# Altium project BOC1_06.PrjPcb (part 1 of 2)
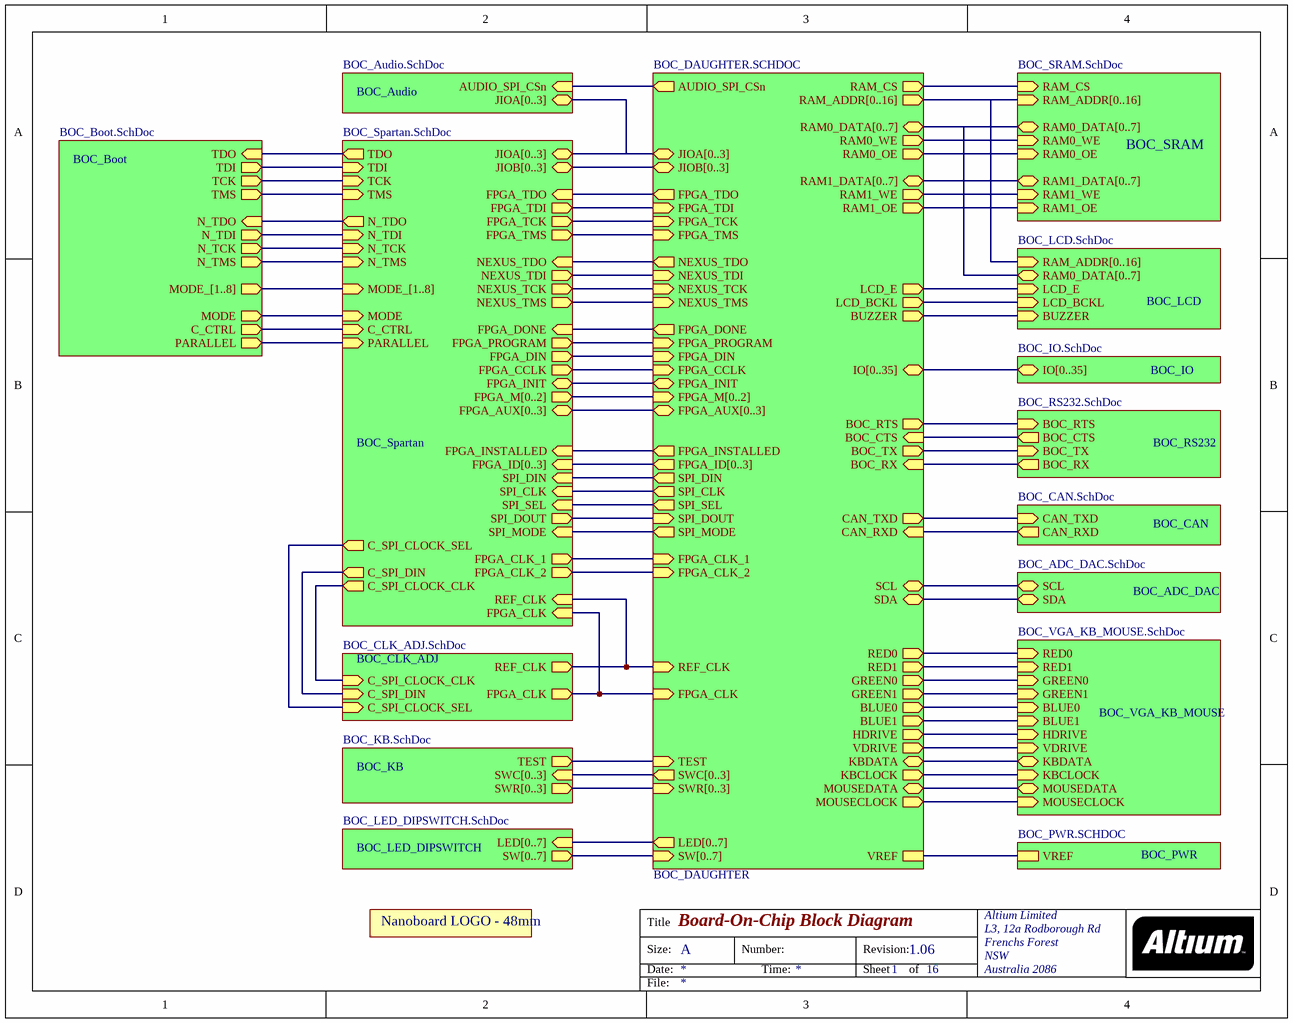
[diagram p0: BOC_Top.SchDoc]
16 sheets, 311 parts. Net scope: hierarchical (ports join the sheet entries above them; power ports are global).
Board file: BOC1_06.PcbDoc
Sheets:
  BOC_Top.SchDoc
    BOC_SRAM = BOC_SRAM.SchDoc
    BOC_IO = BOC_IO.SchDoc
    BOC_KB = BOC_KB.SchDoc
    BOC_PWR = BOC_PWR.SchDoc
    BOC_RS232 = BOC_RS232.SchDoc
    BOC_ADC_DAC = BOC_ADC_DAC.SchDoc
    BOC_CAN = BOC_CAN.SchDoc
    BOC_LED_DIPSWITCH = BOC_LED_DIPSWITCH.SchDoc
    BOC_CLK_ADJ = BOC_CLK_ADJ.SchDoc
    BOC_LCD = BOC_LCD.SchDoc
    BOC_VGA_KB_MOUSE = BOC_VGA_KB_MOUSE.SchDoc
    BOC_Spartan = BOC_Spartan.SchDoc
    BOC_DAUGHTER = BOC_DAUGHTER.SchDoc
    BOC_Boot = BOC_Boot.SchDoc
    BOC_Audio = BOC_Audio.SchDoc

## Sheet BOC_Top.SchDoc: Board-On-Chip Block Diagram
size A; Organization: Altium Limited; Address1: L3, 12a Rodborough Rd; Address2: Frenchs Forest; Address3: NSW; Address4: Australia 2086; Revision: 1.06; SheetNumber: 1; SheetTotal: 16

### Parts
LOGO1  NanoboardLogo48mm  [NanoboardLogo48mm]  (value not drawn)  (graphical)

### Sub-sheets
BOC_ADC_DAC = BOC_ADC_DAC.SchDoc: SCL (bidir), SDA (bidir)
BOC_Audio = BOC_Audio.SchDoc: AUDIO_SPI_CSn (in), JIOA[0..3] (bidir)
BOC_Boot = BOC_Boot.SchDoc: TCK (out), TDO (in), TDI (out), TMS (out), C_CTRL (out), PARALLEL (out), MODE_[1..8] (out), N_TDI (out), N_TDO (in), N_TCK (out), N_TMS (out), MODE (out)
BOC_CAN = BOC_CAN.SchDoc: CAN_TXD (in), CAN_RXD (out)
BOC_CLK_ADJ = BOC_CLK_ADJ.SchDoc: FPGA_CLK (out), REF_CLK (out), C_SPI_CLOCK_SEL (in), C_SPI_DIN (in), C_SPI_CLOCK_CLK (in)
BOC_DAUGHTER = BOC_DAUGHTER.SCHDOC: FPGA_DONE (out), FPGA_PROGRAM (in), FPGA_CCLK (in), FPGA_DIN (in), IO[0..35] (bidir), BOC_RTS (out), BOC_TX (out), BOC_CTS (in), BOC_RX (in), CAN_TXD (out), CAN_RXD (in), JIOA[0..3] (bidir), JIOB[0..3] (bidir), LED[0..7] (out), SW[0..7] (in), LCD_BCKL (out), FPGA_AUX[0..3] (bidir), FPGA_M[0..2] (in), FPGA_TDI (in), FPGA_TCK (in), FPGA_TMS (in), FPGA_TDO (out), RAM_ADDR[0..16] (out), RAM0_DATA[0..7] (bidir), RAM1_DATA[0..7] (bidir), RAM0_OE (out), RAM0_WE (out), RAM1_OE (out), RAM1_WE (out), RAM_CS (out), RED0 (out), RED1 (out), GREEN0 (out), GREEN1 (out), BLUE0 (out), BLUE1 (out), HDRIVE (out), VDRIVE (out), KBDATA (bidir), KBCLOCK (out), MOUSEDATA (bidir), MOUSECLOCK (out), SWC[0..3] (out), SWR[0..3] (in), FPGA_CLK (in), TEST (in), SCL (bidir), SDA (bidir), NEXUS_TDI (in), NEXUS_TCK (in), NEXUS_TMS (in), NEXUS_TDO (out), BUZZER (out), FPGA_INIT (bidir), VREF, SPI_MODE (out), SPI_DOUT (in), SPI_SEL (out), SPI_CLK (out), SPI_DIN (out), FPGA_CLK_1 (in), FPGA_CLK_2 (in), FPGA_INSTALLED (out), REF_CLK (in), FPGA_ID[0..3] (out), LCD_E (out), AUDIO_SPI_CSn (out)
BOC_IO = BOC_IO.SchDoc: IO[0..35] (bidir)
BOC_KB = BOC_KB.SchDoc: SWC[0..3] (in), SWR[0..3] (out), TEST (out)
BOC_LCD = BOC_LCD.SchDoc: RAM0_DATA[0..7] (bidir), LCD_BCKL (in), RAM_ADDR[0..16] (in), BUZZER (in), LCD_E (in)
BOC_LED_DIPSWITCH = BOC_LED_DIPSWITCH.SchDoc: LED[0..7] (in), SW[0..7] (out)
BOC_PWR = BOC_PWR.SCHDOC: VREF
BOC_RS232 = BOC_RS232.SchDoc: BOC_RTS (in), BOC_TX (in), BOC_CTS (out), BOC_RX (out)
BOC_Spartan = BOC_Spartan.SchDoc: FPGA_TDI (out), FPGA_TCK (out), FPGA_TMS (out), FPGA_TDO (in), FPGA_DONE (in), FPGA_PROGRAM (out), FPGA_CCLK (out), FPGA_DIN (out), FPGA_AUX[0..3] (bidir), FPGA_M[0..2] (out), JIOA[0..3] (bidir), JIOB[0..3] (bidir), REF_CLK (in), FPGA_INIT (bidir), NEXUS_TDO (in), NEXUS_TDI (out), NEXUS_TCK (out), NEXUS_TMS (out), FPGA_CLK_1 (out), FPGA_CLK_2 (out), FPGA_INSTALLED (in), SPI_DIN (in), SPI_CLK (in), SPI_SEL (in), SPI_DOUT (out), SPI_MODE (in), C_SPI_CLOCK_CLK (out), C_SPI_DIN (out), C_SPI_CLOCK_SEL (out), FPGA_ID[0..3] (in), TCK (in), TDO (out), TDI (in), TMS (in), C_CTRL (in), PARALLEL (in), MODE_[1..8] (in), N_TDI (in), N_TDO (out), N_TCK (in), N_TMS (in), MODE (in), FPGA_CLK (in)
BOC_SRAM = BOC_SRAM.SchDoc: RAM_ADDR[0..16] (in), RAM1_DATA[0..7] (bidir), RAM0_WE (in), RAM0_OE (in), RAM1_WE (in), RAM1_OE (in), RAM_CS (in), RAM0_DATA[0..7] (bidir)
BOC_VGA_KB_MOUSE = BOC_VGA_KB_MOUSE.SchDoc: RED0 (in), RED1 (in), GREEN0 (in), GREEN1 (in), BLUE0 (in), BLUE1 (in), HDRIVE (in), VDRIVE (in), KBDATA (bidir), KBCLOCK (in), MOUSEDATA (bidir), MOUSECLOCK (in)

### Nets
AUDIO_SPI_CSn: sheet BOC_DAUGHTER/AUDIO_SPI_CSn, sheet BOC_Audio/AUDIO_SPI_CSn
BLUE0: sheet BOC_VGA_KB_MOUSE/BLUE0, sheet BOC_DAUGHTER/BLUE0
BLUE1: sheet BOC_VGA_KB_MOUSE/BLUE1, sheet BOC_DAUGHTER/BLUE1
BOC_CTS: sheet BOC_RS232/BOC_CTS, sheet BOC_DAUGHTER/BOC_CTS
BOC_RTS: sheet BOC_RS232/BOC_RTS, sheet BOC_DAUGHTER/BOC_RTS
BOC_RX: sheet BOC_RS232/BOC_RX, sheet BOC_DAUGHTER/BOC_RX
BOC_TX: sheet BOC_RS232/BOC_TX, sheet BOC_DAUGHTER/BOC_TX
BUZZER: sheet BOC_LCD/BUZZER, sheet BOC_DAUGHTER/BUZZER
C_CTRL: sheet BOC_Spartan/C_CTRL, sheet BOC_Boot/C_CTRL
C_SPI_CLOCK_CLK: sheet BOC_CLK_ADJ/C_SPI_CLOCK_CLK, sheet BOC_Spartan/C_SPI_CLOCK_CLK
C_SPI_CLOCK_SEL: sheet BOC_CLK_ADJ/C_SPI_CLOCK_SEL, sheet BOC_Spartan/C_SPI_CLOCK_SEL
C_SPI_DIN: sheet BOC_CLK_ADJ/C_SPI_DIN, sheet BOC_Spartan/C_SPI_DIN
CAN_RXD: sheet BOC_CAN/CAN_RXD, sheet BOC_DAUGHTER/CAN_RXD
CAN_TXD: sheet BOC_CAN/CAN_TXD, sheet BOC_DAUGHTER/CAN_TXD
FPGA_CCLK: sheet BOC_Spartan/FPGA_CCLK, sheet BOC_DAUGHTER/FPGA_CCLK
FPGA_CLK: sheet BOC_CLK_ADJ/FPGA_CLK, sheet BOC_Spartan/FPGA_CLK, sheet BOC_DAUGHTER/FPGA_CLK
FPGA_CLK_1: sheet BOC_Spartan/FPGA_CLK_1, sheet BOC_DAUGHTER/FPGA_CLK_1
FPGA_CLK_2: sheet BOC_Spartan/FPGA_CLK_2, sheet BOC_DAUGHTER/FPGA_CLK_2
FPGA_DIN: sheet BOC_Spartan/FPGA_DIN, sheet BOC_DAUGHTER/FPGA_DIN
FPGA_DONE: sheet BOC_Spartan/FPGA_DONE, sheet BOC_DAUGHTER/FPGA_DONE
FPGA_INIT: sheet BOC_Spartan/FPGA_INIT, sheet BOC_DAUGHTER/FPGA_INIT
FPGA_INSTALLED: sheet BOC_Spartan/FPGA_INSTALLED, sheet BOC_DAUGHTER/FPGA_INSTALLED
FPGA_PROGRAM: sheet BOC_Spartan/FPGA_PROGRAM, sheet BOC_DAUGHTER/FPGA_PROGRAM
FPGA_TCK: sheet BOC_Spartan/FPGA_TCK, sheet BOC_DAUGHTER/FPGA_TCK
FPGA_TDI: sheet BOC_Spartan/FPGA_TDI, sheet BOC_DAUGHTER/FPGA_TDI
FPGA_TDO: sheet BOC_Spartan/FPGA_TDO, sheet BOC_DAUGHTER/FPGA_TDO
FPGA_TMS: sheet BOC_Spartan/FPGA_TMS, sheet BOC_DAUGHTER/FPGA_TMS
GREEN0: sheet BOC_VGA_KB_MOUSE/GREEN0, sheet BOC_DAUGHTER/GREEN0
GREEN1: sheet BOC_VGA_KB_MOUSE/GREEN1, sheet BOC_DAUGHTER/GREEN1
HDRIVE: sheet BOC_VGA_KB_MOUSE/HDRIVE, sheet BOC_DAUGHTER/HDRIVE
KBCLOCK: sheet BOC_VGA_KB_MOUSE/KBCLOCK, sheet BOC_DAUGHTER/KBCLOCK
KBDATA: sheet BOC_VGA_KB_MOUSE/KBDATA, sheet BOC_DAUGHTER/KBDATA
LCD_BCKL: sheet BOC_LCD/LCD_BCKL, sheet BOC_DAUGHTER/LCD_BCKL
LCD_E: sheet BOC_LCD/LCD_E, sheet BOC_DAUGHTER/LCD_E
MODE: sheet BOC_Spartan/MODE, sheet BOC_Boot/MODE
MOUSECLOCK: sheet BOC_VGA_KB_MOUSE/MOUSECLOCK, sheet BOC_DAUGHTER/MOUSECLOCK
MOUSEDATA: sheet BOC_VGA_KB_MOUSE/MOUSEDATA, sheet BOC_DAUGHTER/MOUSEDATA
N_TCK: sheet BOC_Spartan/N_TCK, sheet BOC_Boot/N_TCK
N_TDI: sheet BOC_Spartan/N_TDI, sheet BOC_Boot/N_TDI
N_TDO: sheet BOC_Spartan/N_TDO, sheet BOC_Boot/N_TDO
N_TMS: sheet BOC_Spartan/N_TMS, sheet BOC_Boot/N_TMS
NEXUS_TCK: sheet BOC_Spartan/NEXUS_TCK, sheet BOC_DAUGHTER/NEXUS_TCK
NEXUS_TDI: sheet BOC_Spartan/NEXUS_TDI, sheet BOC_DAUGHTER/NEXUS_TDI
NEXUS_TDO: sheet BOC_Spartan/NEXUS_TDO, sheet BOC_DAUGHTER/NEXUS_TDO
NEXUS_TMS: sheet BOC_Spartan/NEXUS_TMS, sheet BOC_DAUGHTER/NEXUS_TMS
PARALLEL: sheet BOC_Spartan/PARALLEL, sheet BOC_Boot/PARALLEL
RAM0_OE: sheet BOC_SRAM/RAM0_OE, sheet BOC_DAUGHTER/RAM0_OE
RAM0_WE: sheet BOC_SRAM/RAM0_WE, sheet BOC_DAUGHTER/RAM0_WE
RAM1_OE: sheet BOC_SRAM/RAM1_OE, sheet BOC_DAUGHTER/RAM1_OE
RAM1_WE: sheet BOC_SRAM/RAM1_WE, sheet BOC_DAUGHTER/RAM1_WE
RAM_CS: sheet BOC_SRAM/RAM_CS, sheet BOC_DAUGHTER/RAM_CS
RED0: sheet BOC_VGA_KB_MOUSE/RED0, sheet BOC_DAUGHTER/RED0
RED1: sheet BOC_VGA_KB_MOUSE/RED1, sheet BOC_DAUGHTER/RED1
REF_CLK: sheet BOC_CLK_ADJ/REF_CLK, sheet BOC_Spartan/REF_CLK, sheet BOC_DAUGHTER/REF_CLK
SCL: sheet BOC_ADC_DAC/SCL, sheet BOC_DAUGHTER/SCL
SDA: sheet BOC_ADC_DAC/SDA, sheet BOC_DAUGHTER/SDA
SPI_CLK: sheet BOC_Spartan/SPI_CLK, sheet BOC_DAUGHTER/SPI_CLK
SPI_DIN: sheet BOC_Spartan/SPI_DIN, sheet BOC_DAUGHTER/SPI_DIN
SPI_DOUT: sheet BOC_Spartan/SPI_DOUT, sheet BOC_DAUGHTER/SPI_DOUT
SPI_MODE: sheet BOC_Spartan/SPI_MODE, sheet BOC_DAUGHTER/SPI_MODE
SPI_SEL: sheet BOC_Spartan/SPI_SEL, sheet BOC_DAUGHTER/SPI_SEL
TCK: sheet BOC_Spartan/TCK, sheet BOC_Boot/TCK
TDI: sheet BOC_Spartan/TDI, sheet BOC_Boot/TDI
TDO: sheet BOC_Spartan/TDO, sheet BOC_Boot/TDO
TEST: sheet BOC_KB/TEST, sheet BOC_DAUGHTER/TEST
TMS: sheet BOC_Spartan/TMS, sheet BOC_Boot/TMS
VDRIVE: sheet BOC_VGA_KB_MOUSE/VDRIVE, sheet BOC_DAUGHTER/VDRIVE
VREF: sheet BOC_PWR/VREF, sheet BOC_DAUGHTER/VREF

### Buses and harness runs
bus sheet BOC_Audio/JIOA[0..3] = sheet BOC_DAUGHTER/JIOA[0..3] = sheet BOC_Spartan/JIOA[0..3]
bus sheet BOC_Boot/MODE_[1..8] = sheet BOC_Spartan/MODE_[1..8]
bus sheet BOC_DAUGHTER/FPGA_AUX[0..3] = sheet BOC_Spartan/FPGA_AUX[0..3]
bus sheet BOC_DAUGHTER/FPGA_ID[0..3] = sheet BOC_Spartan/FPGA_ID[0..3]
bus sheet BOC_DAUGHTER/FPGA_M[0..2] = sheet BOC_Spartan/FPGA_M[0..2]
bus sheet BOC_DAUGHTER/IO[0..35] = sheet BOC_IO/IO[0..35]
bus sheet BOC_DAUGHTER/JIOB[0..3] = sheet BOC_Spartan/JIOB[0..3]
bus sheet BOC_DAUGHTER/LED[0..7] = sheet BOC_LED_DIPSWITCH/LED[0..7]
bus sheet BOC_DAUGHTER/RAM0_DATA[0..7] = sheet BOC_LCD/RAM0_DATA[0..7] = sheet BOC_SRAM/RAM0_DATA[0..7]
bus sheet BOC_DAUGHTER/RAM1_DATA[0..7] = sheet BOC_SRAM/RAM1_DATA[0..7]
bus sheet BOC_DAUGHTER/RAM_ADDR[0..16] = sheet BOC_LCD/RAM_ADDR[0..16] = sheet BOC_SRAM/RAM_ADDR[0..16]
bus sheet BOC_DAUGHTER/SW[0..7] = sheet BOC_LED_DIPSWITCH/SW[0..7]
bus sheet BOC_DAUGHTER/SWC[0..3] = sheet BOC_KB/SWC[0..3]
bus sheet BOC_DAUGHTER/SWR[0..3] = sheet BOC_KB/SWR[0..3]

## Sheet BOC_SRAM.SchDoc: Board-On-Chip Static Ram 128k
size A; Organization: Altium Limited; Address1: L3, 12a Rodborough Rd; Address2: Frenchs Forest; Address3: NSW; Address4: Australia 2086; Revision: 1.06; SheetNumber: 9; SheetTotal: 16
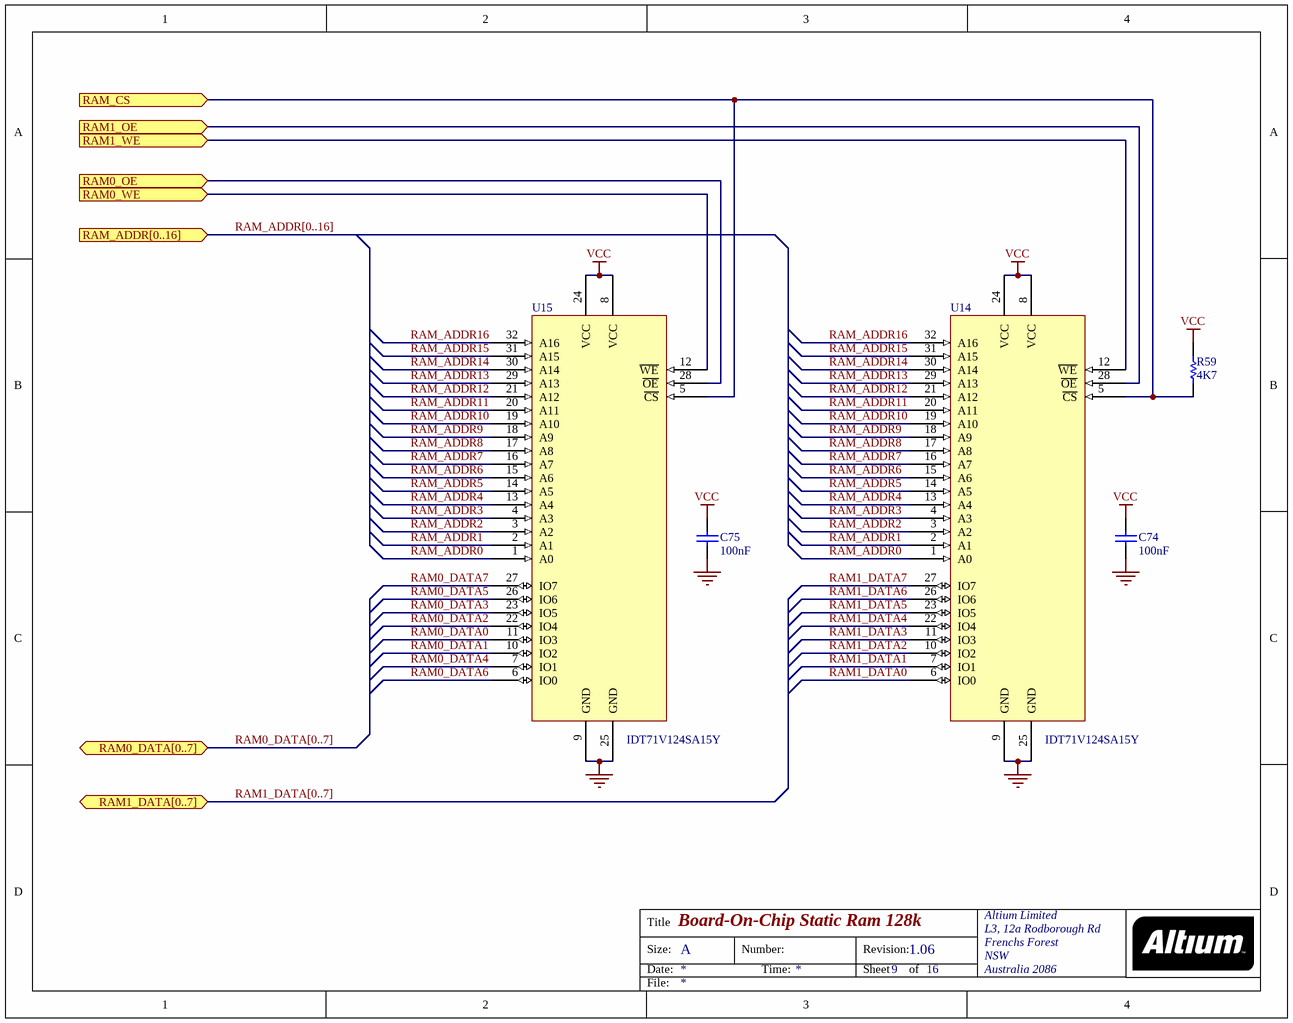
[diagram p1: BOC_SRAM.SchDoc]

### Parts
C74  100nF  [CC2012-0805]
C75  100nF  [CC2012-0805]
R59  4K7  [CC2012-0805]
U14  IDT71V124SA15Y  [SO-J32]
U15  IDT71V124SA15Y  [SO-J32]

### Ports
RAM0_DATA[0..7] (bidir), RAM0_OE (in), RAM0_WE (in), RAM1_DATA[0..7] (bidir), RAM1_OE (in), RAM1_WE (in), RAM_ADDR[0..16] (in), RAM_CS (in)

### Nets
GND: C74.2 C75.2 U14.9(GND) U14.25(GND) U15.9(GND) U15.25(GND)
VCC: C74.1 C75.1 R59.1 U14.8(VCC) U14.24(VCC) U15.8(VCC) U15.24(VCC)
RAM0_DATA0: U15.11(IO3)
RAM0_DATA1: U15.10(IO2)
RAM0_DATA2: U15.22(IO4)
RAM0_DATA3: U15.23(IO5)
RAM0_DATA4: U15.7(IO1)
RAM0_DATA5: U15.26(IO6)
RAM0_DATA6: U15.6(IO0)
RAM0_DATA7: U15.27(IO7)
RAM0_OE: U15.28(~{OE}) ; port RAM0_OE
RAM0_WE: U15.12(~{WE}) ; port RAM0_WE
RAM1_DATA0: U14.6(IO0)
RAM1_DATA1: U14.7(IO1)
RAM1_DATA2: U14.10(IO2)
RAM1_DATA3: U14.11(IO3)
RAM1_DATA4: U14.22(IO4)
RAM1_DATA5: U14.23(IO5)
RAM1_DATA6: U14.26(IO6)
RAM1_DATA7: U14.27(IO7)
RAM1_OE: U14.28(~{OE}) ; port RAM1_OE
RAM1_WE: U14.12(~{WE}) ; port RAM1_WE
RAM_ADDR0: U14.1(A0) U15.1(A0)
RAM_ADDR1: U14.2(A1) U15.2(A1)
RAM_ADDR2: U14.3(A2) U15.3(A2)
RAM_ADDR3: U14.4(A3) U15.4(A3)
RAM_ADDR4: U14.13(A4) U15.13(A4)
RAM_ADDR5: U14.14(A5) U15.14(A5)
RAM_ADDR6: U14.15(A6) U15.15(A6)
RAM_ADDR7: U14.16(A7) U15.16(A7)
RAM_ADDR8: U14.17(A8) U15.17(A8)
RAM_ADDR9: U14.18(A9) U15.18(A9)
RAM_ADDR10: U14.19(A10) U15.19(A10)
RAM_ADDR11: U14.20(A11) U15.20(A11)
RAM_ADDR12: U14.21(A12) U15.21(A12)
RAM_ADDR13: U14.29(A13) U15.29(A13)
RAM_ADDR14: U14.30(A14) U15.30(A14)
RAM_ADDR15: U14.31(A15) U15.31(A15)
RAM_ADDR16: U14.32(A16) U15.32(A16)
RAM_CS: R59.2 U14.5(~{CS}) U15.5(~{CS}) ; port RAM_CS

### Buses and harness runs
bus RAM0_DATA[0..7] = port RAM0_DATA[0..7]
bus RAM1_DATA[0..7] = port RAM1_DATA[0..7]
bus RAM_ADDR[0..16] = port RAM_ADDR[0..16]

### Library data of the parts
C74 C75 = CAP: Capacitor; Fitted: True
R59 = RES: Resistor; Fitted: True
U14 U15 = IDT71V124SA15Y: 128K x 8 bit Fast Static RAM; Fitted: True

## Sheet BOC_IO.SchDoc: Board-On-Chip User Header Ports
size A; Organization: Altium Limited; Address1: L3, 12a Rodborough Rd; Address2: Frenchs Forest; Address3: NSW; Address4: Australia 2086; Revision: 1.06; SheetNumber: 11; SheetTotal: 16
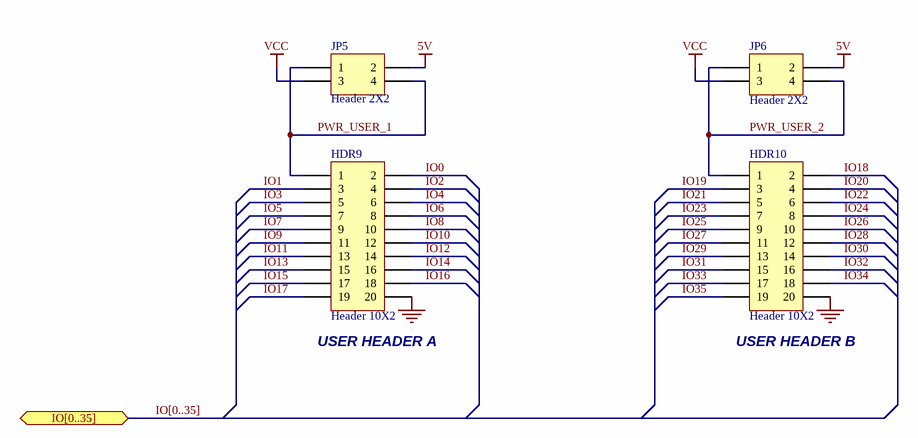
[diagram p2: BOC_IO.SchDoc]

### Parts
HDR9  Header 10X2  [HDR2X10]
HDR10  Header 10X2  [HDR2X10]
JP5  Header 2X2  [HDR2X2_B]
JP6  Header 2X2  [HDR2X2_B]

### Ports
IO[0..35] (bidir)

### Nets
5V: JP5.2 JP6.2
GND: HDR9.20 HDR10.20
VCC: JP5.3 JP6.3
IO0: HDR9.2
IO1: HDR9.3
IO2: HDR9.4
IO3: HDR9.5
IO4: HDR9.6
IO5: HDR9.7
IO6: HDR9.8
IO7: HDR9.9
IO8: HDR9.10
IO9: HDR9.11
IO10: HDR9.12
IO11: HDR9.13
IO12: HDR9.14
IO13: HDR9.15
IO14: HDR9.16
IO15: HDR9.17
IO16: HDR9.18
IO17: HDR9.19
IO18: HDR10.2
IO19: HDR10.3
IO20: HDR10.4
IO21: HDR10.5
IO22: HDR10.6
IO23: HDR10.7
IO24: HDR10.8
IO25: HDR10.9
IO26: HDR10.10
IO27: HDR10.11
IO28: HDR10.12
IO29: HDR10.13
IO30: HDR10.14
IO31: HDR10.15
IO32: HDR10.16
IO33: HDR10.17
IO34: HDR10.18
IO35: HDR10.19
PWR_USER_1: HDR9.1 JP5.1 JP5.4
PWR_USER_2: HDR10.1 JP6.1 JP6.4

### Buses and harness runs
bus IO[0..35] = port IO[0..35]

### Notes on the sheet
- (near HDR9) USER HEADER A
- (near HDR10) USER HEADER B

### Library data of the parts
HDR9 HDR10 = Header 10X2: Header, 10-Pin, Dual row; Manufacturer: Generic Components; Class I: Connector; Fitted: True
JP5 JP6 = Header 2X2: Header, 2-Pin, Dual row; Manufacturer: Generic Components; Class I: Connector; Fitted: True

## Sheet BOC_KB.SchDoc: Board-On-Chip Keyboard
size A; Organization: Altium Limited; Address1: L3, 12a Rodborough Rd; Address2: Frenchs Forest; Address3: NSW; Address4: Australia 2086; Revision: 1.06; SheetNumber: 6; SheetTotal: 16
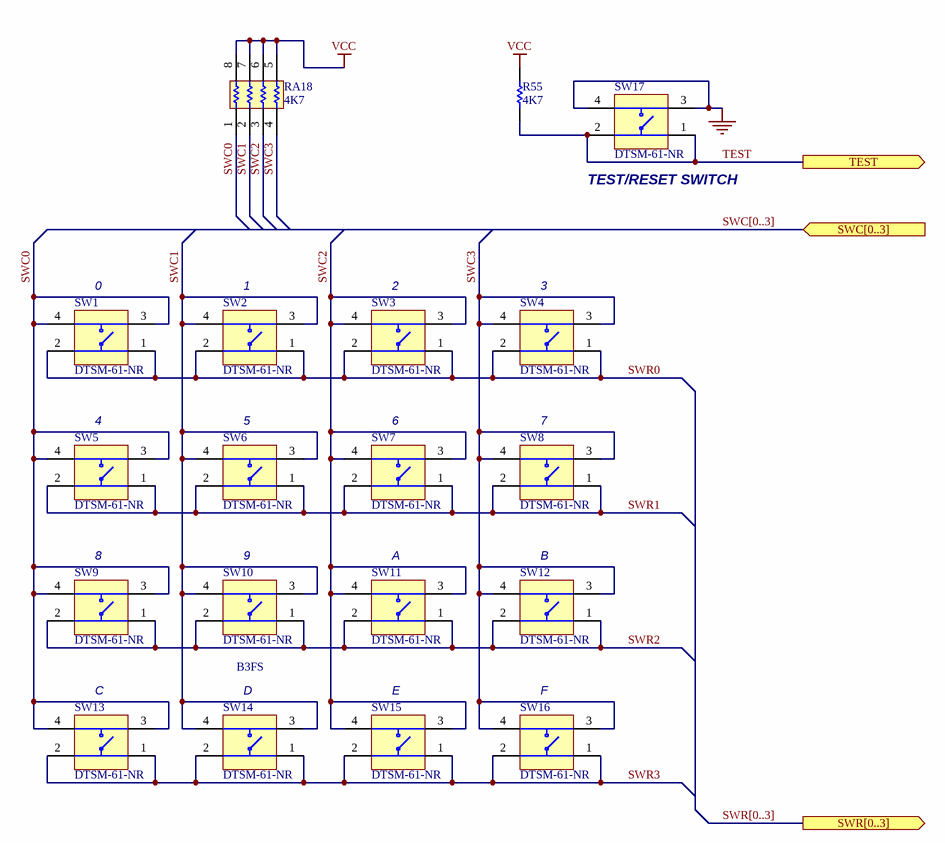
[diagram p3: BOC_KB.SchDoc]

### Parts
R55  4K7  [CC2012-0805]
RA18  4K7  [MNR34]
SW1  DTSM-61-NR  [B3FS_SWITCH]
SW2  DTSM-61-NR  [B3FS_SWITCH]
SW3  DTSM-61-NR  [B3FS_SWITCH]
SW4  DTSM-61-NR  [B3FS_SWITCH]
SW5  DTSM-61-NR  [B3FS_SWITCH]
SW6  DTSM-61-NR  [B3FS_SWITCH]
SW7  DTSM-61-NR  [B3FS_SWITCH]
SW8  DTSM-61-NR  [B3FS_SWITCH]
SW9  DTSM-61-NR  [B3FS_SWITCH]
SW10  DTSM-61-NR  [B3FS_SWITCH]
SW11  DTSM-61-NR  [B3FS_SWITCH]
SW12  DTSM-61-NR  [B3FS_SWITCH]
SW13  DTSM-61-NR  [B3FS_SWITCH]
SW14  DTSM-61-NR  [B3FS_SWITCH]
SW15  DTSM-61-NR  [B3FS_SWITCH]
SW16  DTSM-61-NR  [B3FS_SWITCH]
SW17  DTSM-61-NR  [B3FS_SWITCH]

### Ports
SWC[0..3] (in), SWR[0..3] (out), TEST (out)

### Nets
GND: SW17.3 SW17.4
VCC: R55.1 RA18.5 RA18.6 RA18.7 RA18.8
SWC0: RA18.1 SW1.3 SW1.4 SW5.3 SW5.4 SW9.3 SW9.4 SW13.3 SW13.4
SWC1: RA18.2 SW2.3 SW2.4 SW6.3 SW6.4 SW10.3 SW10.4 SW14.3 SW14.4
SWC2: RA18.3 SW3.3 SW3.4 SW7.3 SW7.4 SW11.3 SW11.4 SW15.3 SW15.4
SWC3: RA18.4 SW4.3 SW4.4 SW8.3 SW8.4 SW12.3 SW12.4 SW16.3 SW16.4
SWR0: SW1.1 SW1.2 SW2.1 SW2.2 SW3.1 SW3.2 SW4.1 SW4.2
SWR1: SW5.1 SW5.2 SW6.1 SW6.2 SW7.1 SW7.2 SW8.1 SW8.2
SWR2: SW9.1 SW9.2 SW10.1 SW10.2 SW11.1 SW11.2 SW12.1 SW12.2
SWR3: SW13.1 SW13.2 SW14.1 SW14.2 SW15.1 SW15.2 SW16.1 SW16.2
TEST: R55.2 SW17.1 SW17.2 ; port TEST

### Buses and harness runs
bus SWC[0..3] = port SWC[0..3]
bus SWR[0..3] = port SWR[0..3]

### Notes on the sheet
- (near SW17) TEST/RESET SWITCH
- (near SW1) 0
- (near SW2) 1
- (near SW3) 2
- (near SW4) 3
- (near SW5) 4
- (near SW6) 5
- (near SW7) 6
- (near SW8) 7
- (near SW9) 8
- (near SW10) 9
- (near SW11) A
- (near SW12) B
- (near SW13) C
- (near SW14) D
- (near SW15) E
- (near SW16) F

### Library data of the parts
R55 = RES: Resistor; Fitted: True
RA18 = MNR34: 3216x4 Resistor Array; Fitted: True
SW1-SW17 = B3FS: SPNA SMD Keyboard Switch; Fitted: True

## Sheet BOC_PWR.SchDoc: Board-On-Chip Power Supply
size A; Organization: Altium Limited; Address1: L3, 12a Rodborough Rd; Address2: Frenchs Forest; Address3: NSW; Address4: Australia 2086; Revision: 1.06; SheetNumber: 16; SheetTotal: 16
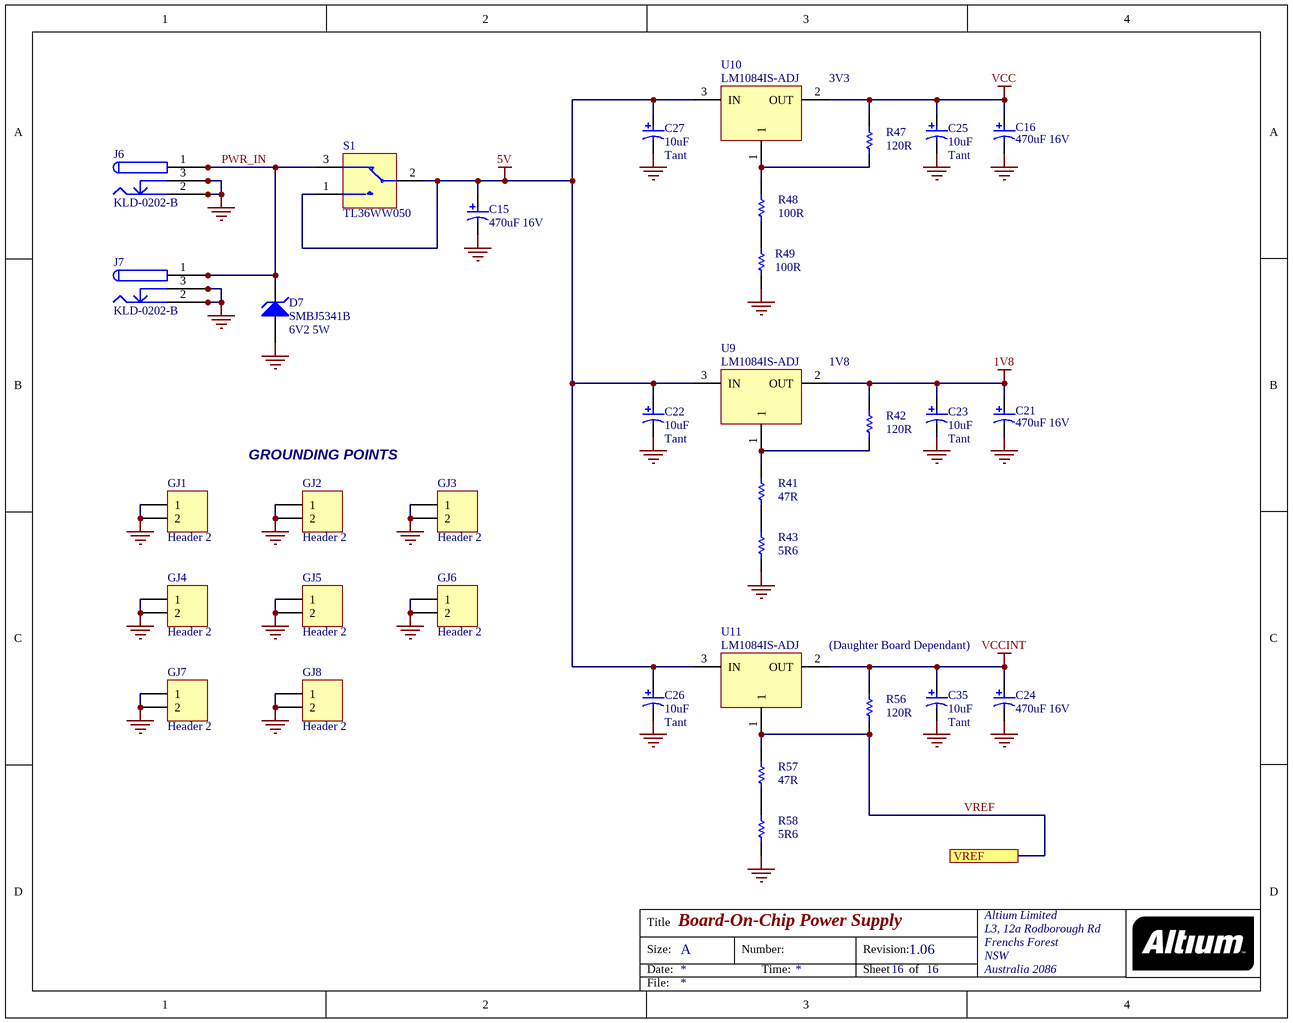
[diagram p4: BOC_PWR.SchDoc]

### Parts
C15  470uF 16V  [RB8/3.5]
C16  470uF 16V  [RB8/3.5]
C21  470uF 16V  [RB8/3.5]
C22  10uF  Capacitor Type: Tant  [MCCT-B]
C23  10uF  Capacitor Type: Tant  [MCCT-B]
C24  470uF 16V  [RB8/3.5]
C25  10uF  Capacitor Type: Tant  [MCCT-B]
C26  10uF  Capacitor Type: Tant  [MCCT-B]
C27  10uF  Capacitor Type: Tant  [MCCT-B]
C35  10uF  Capacitor Type: Tant  [MCCT-B]
D7  SMBJ5341B  Part Description: 6V2 5W  [DO214]
GJ1  Header 2  [HDR1X2]
GJ2  Header 2  [HDR1X2]
GJ3  Header 2  [HDR1X2]
GJ4  Header 2  [HDR1X2]
GJ5  Header 2  [HDR1X2]
GJ6  Header 2  [HDR1X2]
GJ7  Header 2  [HDR1X2]
GJ8  Header 2  [HDR1X2]
J6  KLD-0202-B  [KLD-0202]
J7  KLD-0202-B  [KLD-0202]
R41  47R  [CC2012-0805]
R42  120R  [CC2012-0805]
R43  5R6  [CC2012-0805]
R47  120R  [CC2012-0805]
R48  100R  [CC2012-0805]
R49  100R  [CC2012-0805]
R56  120R  [CC2012-0805]
R57  47R  [CC2012-0805]
R58  5R6  [CC2012-0805]
S1  TL36WW050  [TL36WW15050]
U9  LM1084IS-ADJ  [TO-263]
U10  LM1084IS-ADJ  [TO-263]
U11  LM1084IS-ADJ  [TO-263]

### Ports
VREF

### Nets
1V8: C21.1 C23.1 R42.1 U9.2(OUT)
5V: C15.1 C22.1 C26.1 C27.1 S1.1 S1.2 U9.3(IN) U10.3(IN) U11.3(IN)
GND: C15.2 C16.2 C21.2 C22.2 C23.2 C24.2 C25.2 C26.2 C27.2 C35.2 D7.1(A) GJ1.1 GJ1.2 GJ2.1 GJ2.2 GJ3.1 GJ3.2 GJ4.1 GJ4.2 GJ5.1 GJ5.2 GJ6.1 GJ6.2 GJ7.1 GJ7.2 GJ8.1 GJ8.2 J6.2 J6.2A J6.2B J6.3 J6.3A J6.3B J7.2 J7.2A J7.2B J7.3 J7.3A J7.3B R43.2 R49.1 R58.2
VCC: C16.1 C25.1 R47.1 U10.2(OUT)
VCCINT: C24.1 C35.1 R56.1 U11.2(OUT)
PWR_IN: D7.2(K) J6.1 J6.1A J6.1B J7.1 J7.1A J7.1B S1.3
VREF: R56.2 R57.1 U11.1 ; port VREF
NetR41_1: R41.1 R42.2 U9.1
NetR41_2: R41.2 R43.1
NetR47_2: R47.2 R48.1 U10.1
NetR48_2: R48.2 R49.2
NetR57_2: R57.2 R58.1

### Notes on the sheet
- 3V3
- 1V8
- (near GJ2) GROUNDING POINTS
- (Daughter Board Dependant)

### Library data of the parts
C15 C16 C21-C27 C35 = CAP_POLAR: Polar Capacitor; Fitted: True
D7 = BZG03C13: Zener Diode, 6.2V, 5W; Manufacturer: Microsemi; Fitted: True
GJ1-GJ8 = Header 2: Header, 2-Pin; Manufacturer: Generic Components; Class I: Connector; Fitted: True
J6 J7 = KLD-0202-B: Low Voltage Power Supply Connector; Manufacturer: Kycon; Fitted: True
R41-R43 R47-R49 R56-R58 = RES: Resistor; Fitted: True
S1 = PCB_MOUNT_SWITCH: SPDT Subminiature Toggle Switch; Fitted: True
U9-U11 = LM1084IS-ADJ: 5A Low Dropout Possitive Regulators; Fitted: True

## Sheet BOC_RS232.SchDoc: Board-On-Chip RS232 Serial Interface
size A; Organization: Altium Limited; Address1: L3, 12a Rodborough Rd; Address2: Frenchs Forest; Address3: NSW; Address4: Australia 2086; Revision: 1.06; SheetNumber: 12; SheetTotal: 16
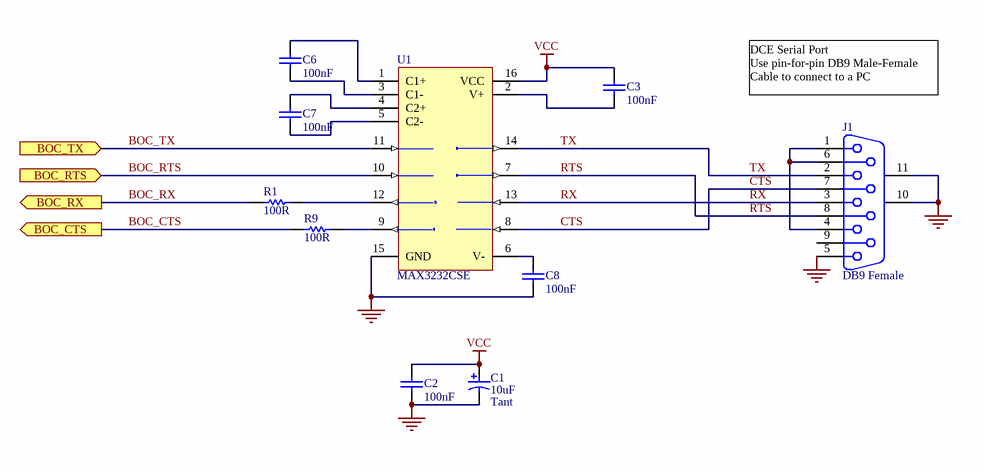
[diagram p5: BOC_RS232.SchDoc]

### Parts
C1  10uF  Capacitor Type: Tant  [MCCT-B]
C2  100nF  [CC2012-0805]
C3  100nF  [CC2012-0805]
C6  100nF  [CC2012-0805]
C7  100nF  [CC2012-0805]
C8  100nF  [CC2012-0805]
J1  DB9 Female  [DSUB1.385-2H9]
R1  100R  [CC2012-0805]
R9  100R  [CC2012-0805]
U1  MAX3232CSE  [SO-G16]

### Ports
BOC_CTS (out), BOC_RTS (in), BOC_RX (out), BOC_TX (in)

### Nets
GND: C1.2 C2.2 C8.2 J1.5 J1.10(MH1) J1.11(MH2) U1.15(GND)
VCC: C1.1 C2.1 C3.1 U1.16(VCC)
BOC_CTS: R9.1 ; port BOC_CTS
BOC_RTS: U1.10(T2IN) ; port BOC_RTS
BOC_RX: R1.1 ; port BOC_RX
BOC_TX: U1.11(T1IN) ; port BOC_TX
CTS: J1.7 U1.8(R2IN)
RTS: J1.8 U1.7(T2OUT)
RX: J1.3 U1.13(R1IN)
TX: J1.2 U1.14(T1OUT)
NetC3_2: C3.2 U1.2(V+)
NetC6_1: C6.1 U1.1(C1+)
NetC6_2: C6.2 U1.3(C1-)
NetC7_1: C7.1 U1.4(C2+)
NetC7_2: C7.2 U1.5(C2-)
NetC8_1: C8.1 U1.6(V-)
NetJ1_1: J1.1 J1.4 J1.6
NetR1_2: R1.2 U1.12(R1OUT)
NetR9_2: R9.2 U1.9(R2OUT)

Not connected (* = marked no-connect by the designer): J1 9

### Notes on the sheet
- DCE Serial Port
  Use pin-for-pin DB9 Male-Female
  Cable to connect to a PC

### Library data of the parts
C1 = CAP_POLAR: Polar Capacitor; Fitted: True
C2 C3 C6-C8 = CAP: Capacitor; Fitted: True
J1 = D Connector 9: Receptacle Assembly, 9 Position, Right Angle; Manufacturer: Generic Components; Package Information: Latest Revision: O; Positions: 9; Fitted: True
R1 R9 = RES: Resistor; Fitted: True
U1 = MAX3232EUE: 3.0V TO 5.5V, Low-Power, up to 1Mbps, True RS-232 Transceiver Using Four 0.1µF External Capacitor; Manufacturer: Maxim,ST; Package Information: Latest Revision: 21-0066 C; Class I: Communication

## Sheet BOC_ADC_DAC.SchDoc: Board-On-Chip Analog Interface
size A; Organization: Altium Limited; Address1: L3, 12a Rodborough Rd; Address2: Frenchs Forest; Address3: NSW; Address4: Australia 2086; Revision: 1.06; SheetNumber: 14; SheetTotal: 16
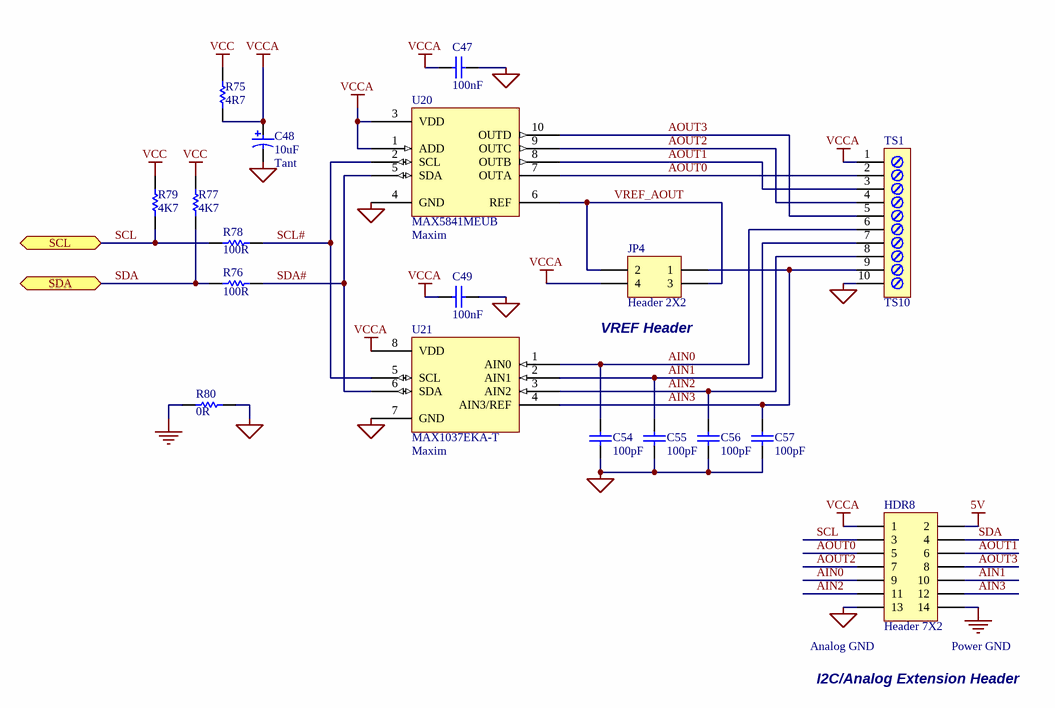
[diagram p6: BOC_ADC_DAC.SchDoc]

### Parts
C47  100nF  [CC2012-0805]
C48  10uF  Capacitor Type: Tant  [MCCT-B]
C49  100nF  [CC2012-0805]
C54  100pF  [CC2012-0805]
C55  100pF  [CC2012-0805]
C56  100pF  [CC2012-0805]
C57  100pF  [CC2012-0805]
HDR8  Header 7X2  [HDR2X7]
JP4  Header 2X2  [HDR2X2_B]
R75  4R7  [CC2012-0805]
R76  100R  [CC2012-0805]
R77  4K7  [CC2012-0805]
R78  100R  [CC2012-0805]
R79  4K7  [CC2012-0805]
R80  0R  [CC2012-0805]
TS1  TS10  [TS2.54x10]
U20  MAX5841MEUB  Supplier: Maxim  [uSOP10]
U21  MAX1037EKA-T  Manufacturer: Maxim  [SOT23_8]

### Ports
SCL (bidir), SDA (bidir)

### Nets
5V: HDR8.2
AGND: C47.2 C48.2 C49.2 C54.2 C55.2 C56.2 C57.2 HDR8.13 R80.2 TS1.10 U20.4(GND) U21.7(GND)
GND: HDR8.14 R80.1
VCC: R75.2 R77.1 R79.1
VCCA: C47.1 C48.1 C49.1 HDR8.1 JP4.4 R75.1 TS1.1 U20.1(ADD) U20.3(VDD) U21.8(VDD)
AIN0: C54.1 HDR8.9 TS1.6 U21.1(AIN0)
AIN1: C55.1 HDR8.10 TS1.7 U21.2(AIN1)
AIN2: C56.1 HDR8.11 TS1.8 U21.3(AIN2)
AIN3: C57.1 HDR8.12 JP4.1 TS1.9 U21.4(AIN3/REF)
AOUT0: HDR8.5 TS1.2 U20.7(OUTA)
AOUT1: HDR8.6 TS1.3 U20.8(OUTB)
AOUT2: HDR8.7 TS1.4 U20.9(OUTC)
AOUT3: HDR8.8 TS1.5 U20.10(OUTD)
SCL: HDR8.3 R78.1 R79.2 ; port SCL
SCL#: R78.2 U20.2(SCL) U21.5(SCL)
SDA: HDR8.4 R76.1 R77.2 ; port SDA
SDA#: R76.2 U20.5(SDA) U21.6(SDA)
VREF_AOUT: JP4.2 JP4.3 U20.6(REF)

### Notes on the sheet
- (near JP4) VREF Header
- (near HDR8) Analog GND
- I2C/Analog Extension Header
- (near HDR8) Power GND

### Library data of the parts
C47 C49 C54-C57 = CAP: Capacitor; Fitted: True
C48 = CAP_POLAR: Polar Capacitor; Fitted: True
HDR8 = Header 7X2: Header, 7-Pin, Dual row; Manufacturer: Generic Components; Class I: Connector; Fitted: True
JP4 = Header 2X2: as JP5 on sheet BOC_IO
R75-R80 = RES: Resistor; Fitted: True
TS1 = TS10: Screw Terminal Strip, 10 Way, 2.54 mm Pitch; Fitted: True
U20 = MAX5841: 4 Channel DAC,I2C,2.7V to 5.5V; Fitted: True
U21 = MAX1037: 4 Channel 8 Bit ADC, I2C interface, 2.7V to 3.6V Supply; Fitted: True

## Sheet BOC_CAN.SchDoc: Board-On-Chip CAN Interface
size A; Organization: Altium Limited; Address1: L3, 12a Rodborough Rd; Address2: Frenchs Forest; Address3: NSW; Address4: Australia 2086; Revision: 1.06; SheetNumber: 13; SheetTotal: 16
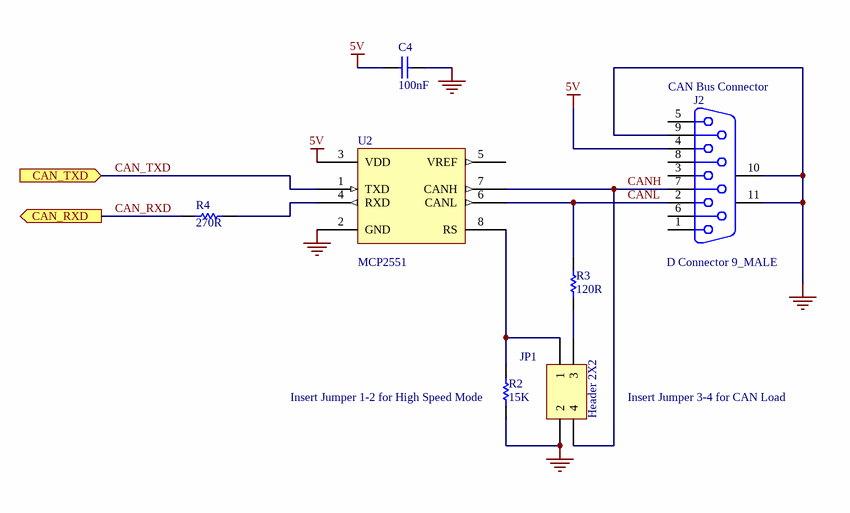
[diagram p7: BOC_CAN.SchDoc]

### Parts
C4  100nF  [CC2012-0805]
J2  D Connector 9_MALE  [DSUB1.9_MALE]
JP1  Header 2X2  [HDR2X2]
R2  15K  [CC2012-0805]
R3  120R  [CC2012-0805]
R4  270R  [CC2012-0805]
U2  MCP2551  [SOIC8]

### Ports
CAN_RXD (out), CAN_TXD (in)

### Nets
5V: C4.1 J2.4 U2.3(VDD)
GND: C4.2 J2.9 J2.10(MH1) J2.11(MH2) JP1.2 R2.1 U2.2(GND)
CAN_RXD: R4.1 ; port CAN_RXD
CAN_TXD: U2.1(TXD) ; port CAN_TXD
CANH: J2.7 JP1.4 U2.7(CANH)
CANL: J2.2 R3.2 U2.6(CANL)
NetJP1_1: JP1.1 R2.2 U2.8(RS)
NetJP1_3: JP1.3 R3.1
NetR4_2: R4.2 U2.4(RXD)

Not connected (* = marked no-connect by the designer): J2 1 3 5 6 8; U2 5(VREF)

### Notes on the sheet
- (near J2) CAN Bus Connector
- (near R2) Insert Jumper 1-2 for High Speed Mode
- Insert Jumper 3-4 for CAN Load

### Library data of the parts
C4 = CAP: Capacitor; Fitted: True
J2 = D Connector 9_MALE: Receptacle Assembly, 9 Position, Right Angle; Manufacturer: Generic Components; Package Information: Latest Revision: O; Positions: 9; Fitted: True
JP1 = Header 2X2: as JP5 on sheet BOC_IO
R2-R4 = RES: Resistor; Fitted: True
U2 = MCP2551: High Speed Can Transceiver; Fitted: True

## Sheet BOC_LED_DIPSWITCH.SchDoc: Board-On-Chip LEDs and DIP Switch
size A; Organization: Altium Limited; Address1: L3, 12a Rodborough Rd; Address2: Frenchs Forest; Address3: NSW; Address4: Australia 2086; Revision: 1.06; SheetNumber: 7; SheetTotal: 16
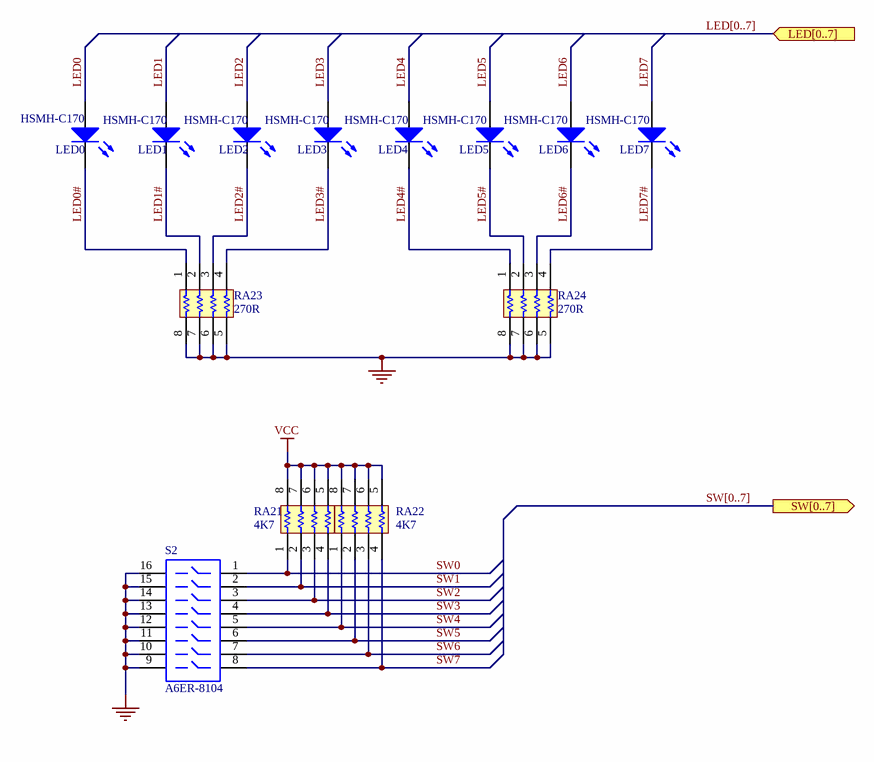
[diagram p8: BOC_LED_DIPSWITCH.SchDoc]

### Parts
LED0  HSMH-C170  [SMD _LED]
LED1  HSMH-C170  [SMD _LED]
LED2  HSMH-C170  [SMD _LED]
LED3  HSMH-C170  [SMD _LED]
LED4  HSMH-C170  [SMD _LED]
LED5  HSMH-C170  [SMD _LED]
LED6  HSMH-C170  [SMD _LED]
LED7  HSMH-C170  [SMD _LED]
RA21  4K7  [MNR34]
RA22  4K7  [MNR34]
RA23  270R  [MNR34]
RA24  270R  [MNR34]
S2  A6ER-8104  [DIP-16-KEY]

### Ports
LED[0..7] (in), SW[0..7] (out)

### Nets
GND: RA23.5 RA23.6 RA23.7 RA23.8 RA24.5 RA24.6 RA24.7 RA24.8 S2.9 S2.10 S2.11 S2.12 S2.13 S2.14 S2.15 S2.16
VCC: RA21.5 RA21.6 RA21.7 RA21.8 RA22.5 RA22.6 RA22.7 RA22.8
LED0: LED0.1(A)
LED0#: LED0.2(K) RA23.1
LED1: LED1.1(A)
LED1#: LED1.2(K) RA23.2
LED2: LED2.1(A)
LED2#: LED2.2(K) RA23.3
LED3: LED3.1(A)
LED3#: LED3.2(K) RA23.4
LED4: LED4.1(A)
LED4#: LED4.2(K) RA24.1
LED5: LED5.1(A)
LED5#: LED5.2(K) RA24.2
LED6: LED6.1(A)
LED6#: LED6.2(K) RA24.3
LED7: LED7.1(A)
LED7#: LED7.2(K) RA24.4
SW0: RA21.1 S2.1
SW1: RA21.2 S2.2
SW2: RA21.3 S2.3
SW3: RA21.4 S2.4
SW4: RA22.1 S2.5
SW5: RA22.2 S2.6
SW6: RA22.3 S2.7
SW7: RA22.4 S2.8

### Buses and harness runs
bus LED[0..7] = port LED[0..7]
bus SW[0..7] = port SW[0..7]

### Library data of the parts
LED0-LED7 = HSMX-C670: Typical RED GaAs SMD LED Agilent make; Manufacturer: Generic Components; Class I: Optoelectronic; Fitted: True
RA21-RA24 = MNR34: 3216x4 Resistor Array; Fitted: True
S2 = A6ER-8104: DIP Switch Side actuator long liver Piano Key; Manufacturer: Generic Components; Fitted: True

## Sheet BOC_CLK_ADJ.SchDoc: Board-On-Chip System Clock
size A; Organization: Altium Limited; Address1: L3, 12a Rodborough Rd; Address2: Frenchs Forest; Address3: NSW; Address4: Australia 2086; Revision: 1.06; SheetNumber: 5; SheetTotal: 16
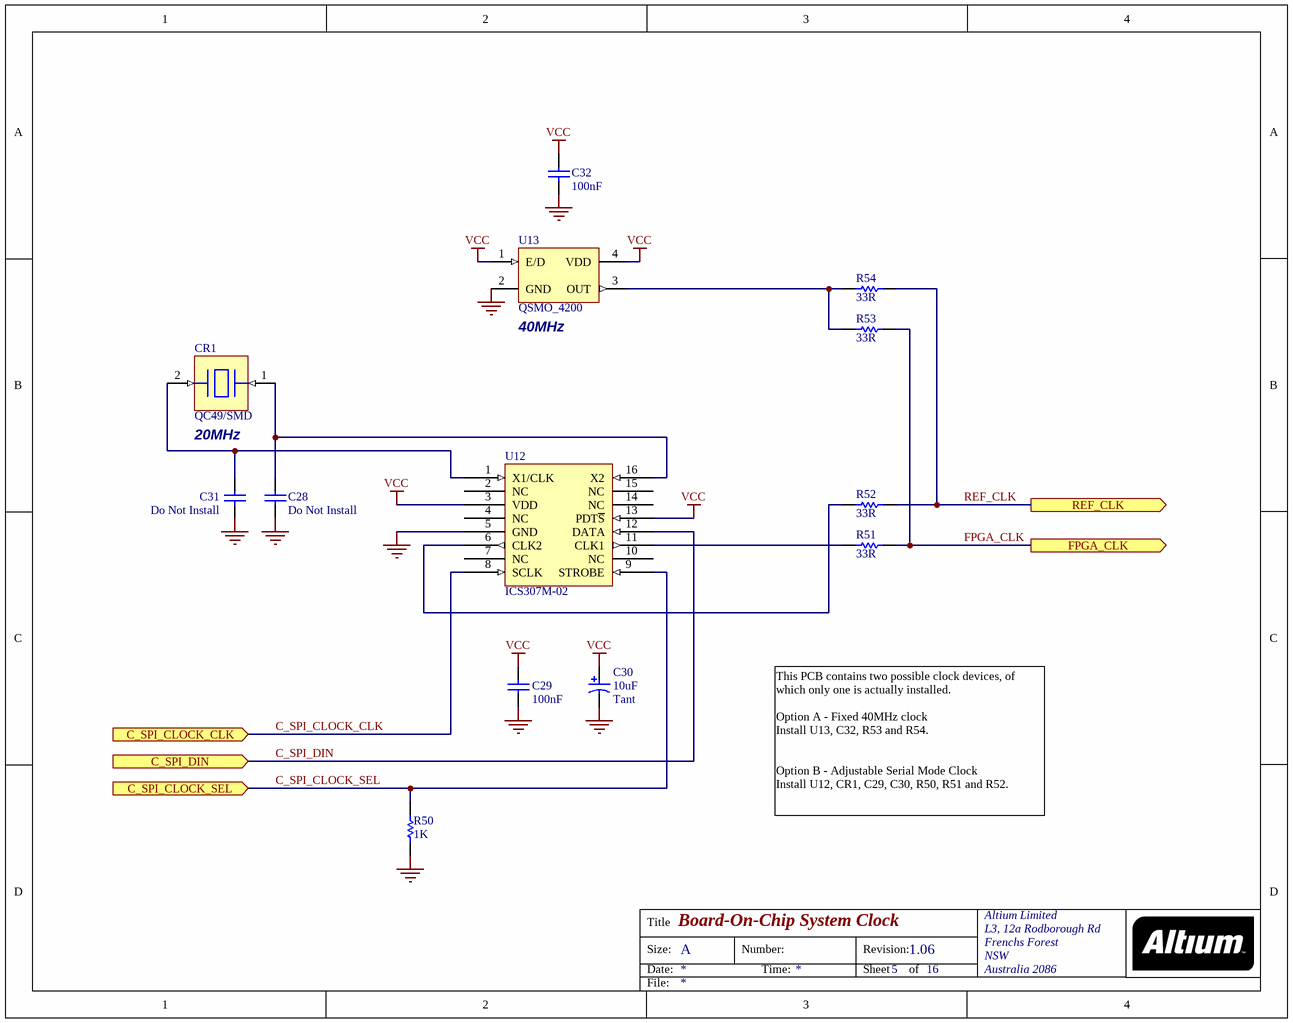
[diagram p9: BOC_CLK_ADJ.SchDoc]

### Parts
C28  Do Not Install  [CC2012-0805]
C29  100nF  [CC2012-0805]
C30  10uF  Capacitor Type: Tant  [MCCT-B]
C31  Do Not Install  [CC2012-0805]
C32  100nF  [CC2012-0805]
CR1  QC49/SMD  [QC49/SMD]
R50  1K  [CC2012-0805]
R51  33R  [CC2012-0805]
R52  33R  [CC2012-0805]
R53  33R  [CC2012-0805]
R54  33R  [CC2012-0805]
U12  ICS307M-02  [SO-G16]
U13  QSMO_4200  [QSMO_4200]

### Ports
C_SPI_CLOCK_CLK (in), C_SPI_CLOCK_SEL (in), C_SPI_DIN (in), FPGA_CLK (out), REF_CLK (out)

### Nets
GND: C28.2 C29.2 C30.2 C31.2 C32.2 R50.2 U12.5(GND) U13.2(GND)
VCC: C29.1 C30.1 C32.1 U12.3(VDD) U12.13(PDT~{S}) U13.1(E/D) U13.4(VDD)
C_SPI_CLOCK_CLK: U12.8(SCLK) ; port C_SPI_CLOCK_CLK
C_SPI_CLOCK_SEL: R50.1 U12.9(STROBE) ; port C_SPI_CLOCK_SEL
C_SPI_DIN: U12.12(DATA) ; port C_SPI_DIN
FPGA_CLK: R51.2 R53.2 ; port FPGA_CLK
REF_CLK: R52.2 R54.2 ; port REF_CLK
NetC28_1: C28.1 CR1.1 U12.16(X2)
NetC31_1: C31.1 CR1.2 U12.1(X1/CLK)
NetR51_1: R51.1 U12.11(CLK1)
NetR52_1: R52.1 U12.6(CLK2)
NetR53_1: R53.1 R54.1 U13.3(OUT)

Not connected (* = marked no-connect by the designer): U12 2(NC) 4(NC) 7(NC) 10(NC) 14(NC) 15(NC)

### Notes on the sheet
- (near U13) 40MHz
- 20MHz
- This PCB contains two possible clock devices, of which only one is actually installed.
  Option A - Fixed 40MHz clock
  Install U13, C32, R53 and R54.
  Option B - Adjustable Serial Mode Clock
  Install U12, CR1, C29, C30, R50, R51 and R52.

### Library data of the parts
C28 C31 C32 = CAP: Capacitor; Fitted: False
C29 = CAP: Capacitor; Fitted: True
C30 = CAP_POLAR: Polar Capacitor; Fitted: True
CR1 = QC49/SMD: SMD Crystal 20MHz HY-Q; Fitted: True
R50-R52 = RES: Resistor; Fitted: True
R53 R54 = RES: Resistor; Fitted: False
U12 = ICS307-02: Serial Programmable PLL Oscillator; Fitted: True
U13 = QSMO_4200: Surface Mount Crystal Oscillator; Fitted: False

## Sheet BOC_LCD.SchDoc: Board-On-Chip LCD Display
size A; Organization: Altium Limited; Address1: L3, 12a Rodborough Rd; Address2: Frenchs Forest; Address3: NSW; Address4: Australia 2086; Revision: 1.06; SheetNumber: 10; SheetTotal: 16
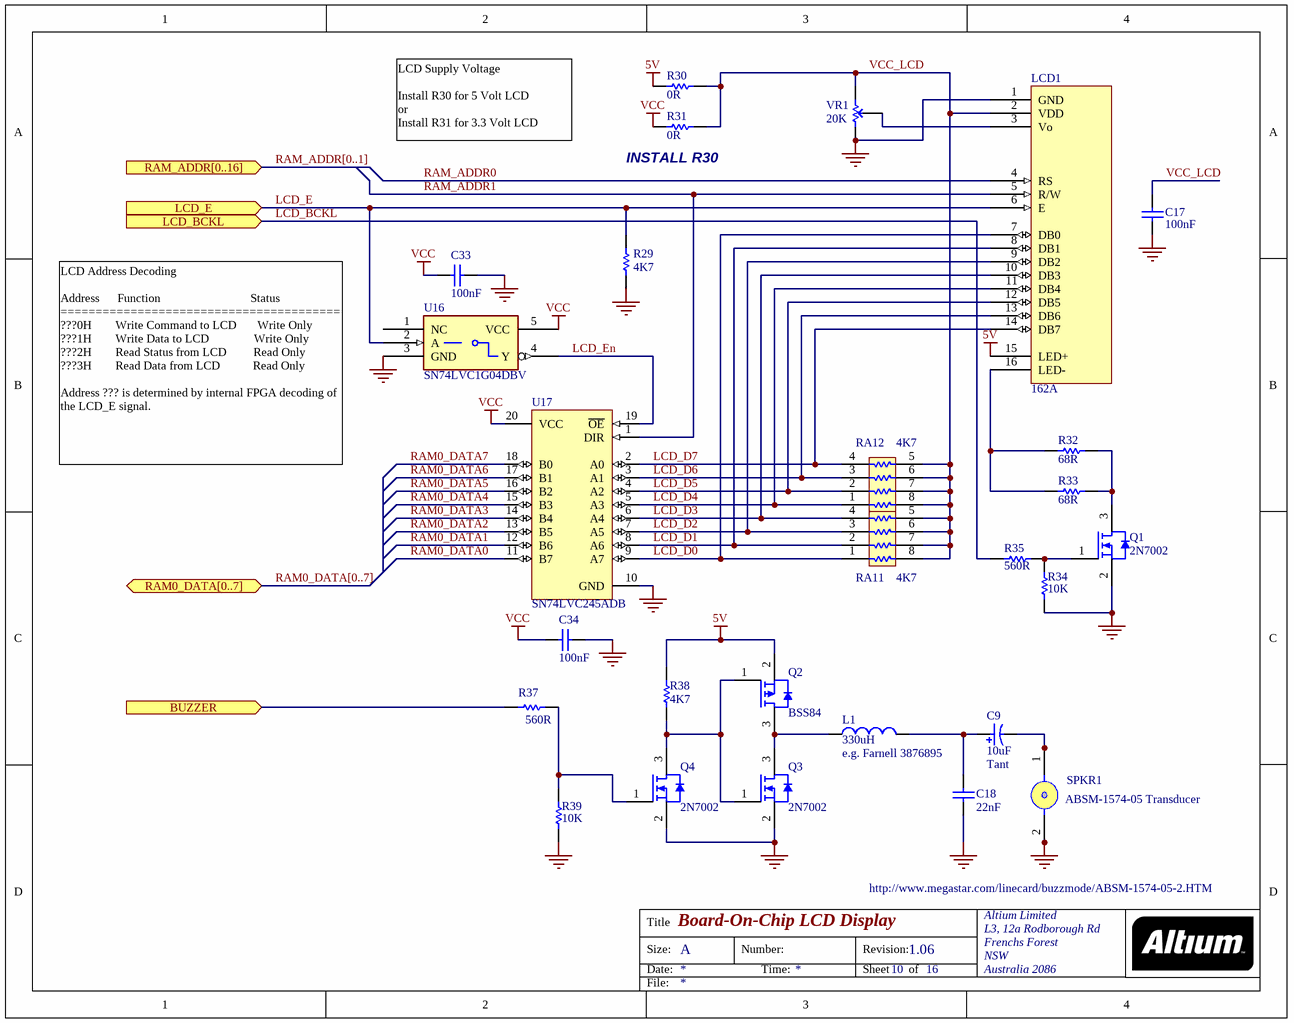
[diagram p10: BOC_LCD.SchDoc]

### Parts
C9  10uF  Capacitor Type: Tant  [MCCT-B]
C17  100nF  [CC2012-0805]
C18  22nF  [CC2012-0805]
C33  100nF  [CC2012-0805]
C34  100nF  [CC2012-0805]
L1  330uH  Part No: e.g. Farnell 3876895  [CC4532-1812]
LCD1  162A  [162A]
Q1  2N7002  [SO-G3]
Q2  BSS84  [SO-G3]
Q3  2N7002  [SO-G3]
Q4  2N7002  [SO-G3]
R29  4K7  [CC2012-0805]
R30  0R  [CC2012-0805]
R31  0R  [CC2012-0805]
R32  68R  [CC2012-0805]
R33  68R  [CC2012-0805]
R34  10K  [CC2012-0805]
R35  560R  [CC2012-0805]
R37  560R  [CC2012-0805]
R38  4K7  [CC2012-0805]
R39  10K  [CC2012-0805]
RA11  4K7  [MNR34]
RA12  4K7  [MNR34]
SPKR1  ABSM-1574-05 Transducer  [ABSM-1574]
U16  SN74LVC1G04DBV  [SO-G5/P.95]
U17  SN74LVC245ADB  [SSO-G20/P.65]
VR1  20K  [POT4MM-2]

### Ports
BUZZER (in), LCD_BCKL (in), LCD_E (in), RAM0_DATA[0..7] (bidir), RAM_ADDR[0..16] (in)

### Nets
5V: LCD1.15(LED+) Q2.2 R30.1 R38.1
GND: C17.2 C18.2 C33.2 C34.2 LCD1.1(GND) Q1.2 Q3.2 Q4.2 R29.2 R34.1 R39.2 SPKR1.2 SPKR1.2A U16.3(GND) U17.10(GND) VR1.CCW(-)
VCC: C33.1 C34.1 R31.1 U16.5(VCC) U17.20(VCC)
BUZZER: R37.1 ; port BUZZER
LCD_BCKL: R35.1 ; port LCD_BCKL
LCD_D0: LCD1.7(DB0) RA11.1 U17.9(A7)
LCD_D1: LCD1.8(DB1) RA11.2 U17.8(A6)
LCD_D2: LCD1.9(DB2) RA11.3 U17.7(A5)
LCD_D3: LCD1.10(DB3) RA11.4 U17.6(A4)
LCD_D4: LCD1.11(DB4) RA12.1 U17.5(A3)
LCD_D5: LCD1.12(DB5) RA12.2 U17.4(A2)
LCD_D6: LCD1.13(DB6) RA12.3 U17.3(A1)
LCD_D7: LCD1.14(DB7) RA12.4 U17.2(A0)
LCD_E: LCD1.6(E) R29.1 U16.2(A) ; port LCD_E
LCD_En: U16.4(Y) U17.19(~{OE})
RAM0_DATA0: U17.11(B7)
RAM0_DATA1: U17.12(B6)
RAM0_DATA2: U17.13(B5)
RAM0_DATA3: U17.14(B4)
RAM0_DATA4: U17.15(B3)
RAM0_DATA5: U17.16(B2)
RAM0_DATA6: U17.17(B1)
RAM0_DATA7: U17.18(B0)
RAM_ADDR0: LCD1.4(RS)
RAM_ADDR1: LCD1.5(R/W) U17.1(DIR)
VCC_LCD: C17.1 LCD1.2(VDD) R30.2 R31.2 RA11.5 RA11.6 RA11.7 RA11.8 RA12.5 RA12.6 RA12.7 RA12.8 VR1.CW(+)
NetC9_1: C9.1 C18.1 L1.2
NetC9_2: C9.2 SPKR1.1 SPKR1.1A
NetL1_1: L1.1 Q2.3 Q3.3
NetLCD1_3: LCD1.3(Vo) VR1.W
NetLCD1_16: LCD1.16(LED-) R32.1 R33.1
NetQ1_1: Q1.1 R34.2 R35.2
NetQ1_3: Q1.3 R32.2 R33.2
NetQ2_1: Q2.1 Q3.1 Q4.3 R38.2
NetQ4_1: Q4.1 R37.2 R39.1

Not connected (* = marked no-connect by the designer): U16 1(NC)

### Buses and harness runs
bus RAM0_DATA[0..7] = port RAM0_DATA[0..7]
bus RAM_ADDR[0..1] = port RAM_ADDR[0..16]

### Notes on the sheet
- LCD Supply Voltage
  Install R30 for 5 Volt LCD
  or
  Install R31 for 3.3 Volt LCD
- (near R31) INSTALL R30
- LCD Address Decoding
  Address      Function                              Status
  ========================================
  ???0H        Write Command to LCD       Write Only
  ???1H        Write Data to LCD               Write Only
  ???2H        Read Status from LCD         Read Only
  ???3H        Read Data from LCD           Read Only
  Address ??? is determined by internal FPGA decoding of the LCD_E signal.

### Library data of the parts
C9 = CAP_POLAR: Polar Capacitor; Fitted: True
C17 C18 C33 C34 = CAP: Capacitor; Fitted: True
L1 = INDUCTOR: Inductor e.g. Farnell 3876895; Fitted: True
LCD1 = 162A: 16 char * 2 line LCD character display with b/light; Fitted: True
Q1 Q3 Q4 = 2N7002: N Channel Mosfet; Fitted: True
Q2 = BSS84: P Channel Mosfet; Fitted: True
R29 R30 R32-R35 R37-R39 = RES: Resistor; Fitted: True
R31 = RES: Resistor; Fitted: False
RA11 RA12 = MNR34: 3216x4 Resistor Array; Fitted: True
SPKR1 = ABSM-1574-05 Transducer: Megastar Subminiature Transducer; Fitted: True
U16 = SN74AHC1G04DBVR: Manufacturer: TI; Fitted: True
U17 = 74LVC245A: Octal Bus Transceiver with 3-State Outputs; Manufacturer: Texas Instruments; Revision 1: 12-July-2000: SIM Model Added.; Revision 2: July-2002: Re-released for DXP Platform.; Class I: Interface; Class II: Line Transceiver; Fitted: True
VR1 = POT_M: Potentiometer; Fitted: True

## Sheet BOC_VGA_KB_MOUSE.SchDoc: Board-On-Chip VGA, KB, and Mouse
size A; Organization: Altium Limited; Address1: L3, 12a Rodborough Rd; Address2: Frenchs Forest; Address3: NSW; Address4: Australia 2086; Revision: 1.06; SheetNumber: 15; SheetTotal: 16
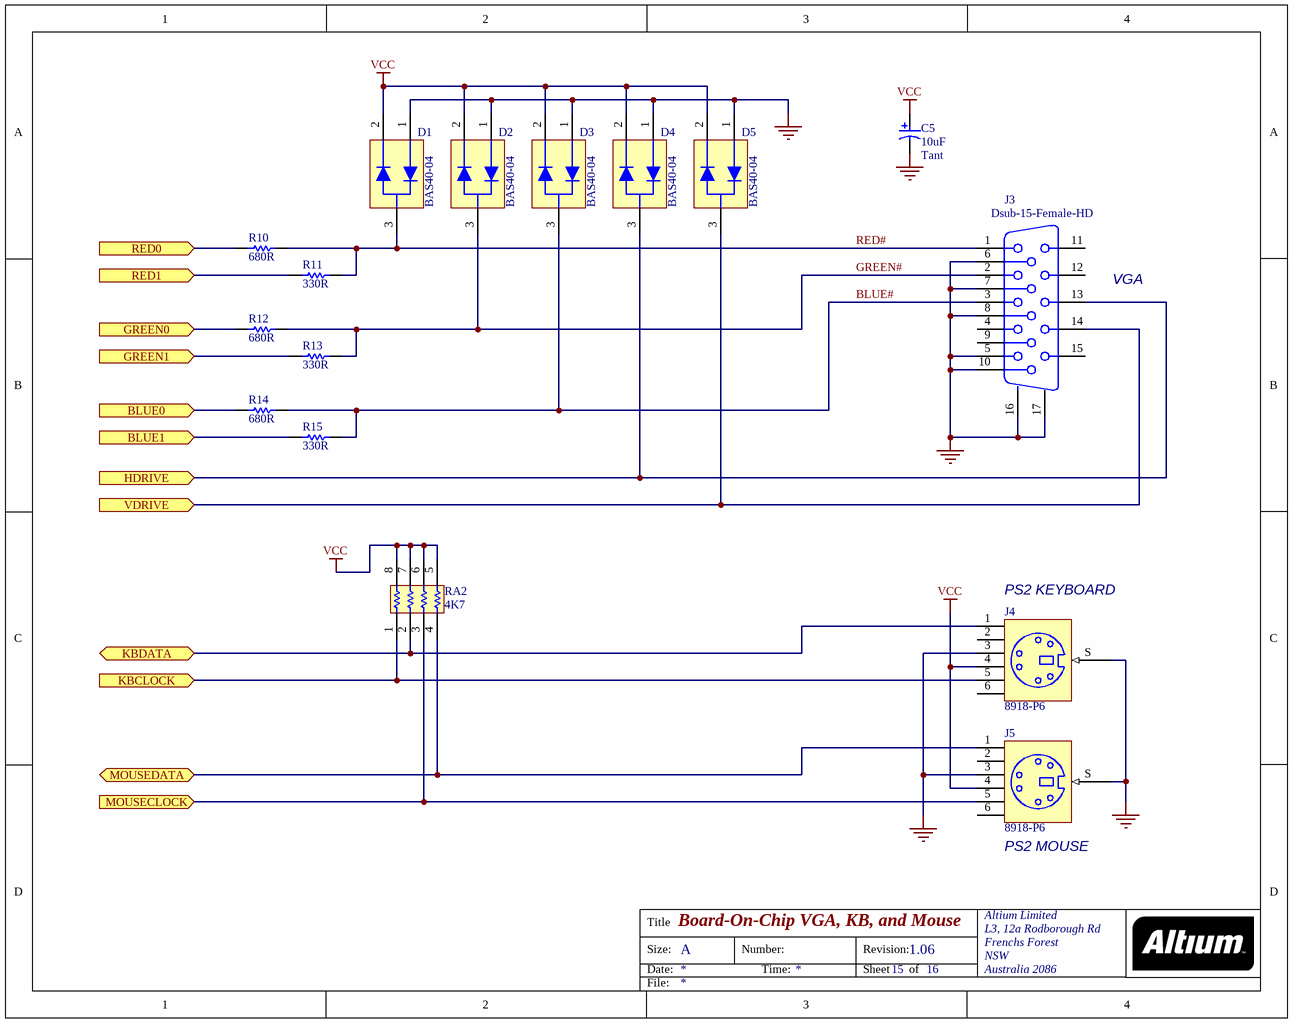
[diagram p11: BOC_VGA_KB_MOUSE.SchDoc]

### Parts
C5  10uF  Capacitor Type: Tant  [MCCT-B]
D1  BAS40-04  [SO-G3]
D2  BAS40-04  [SO-G3]
D3  BAS40-04  [SO-G3]
D4  BAS40-04  [SO-G3]
D5  BAS40-04  [SO-G3]
J3  Dsub-15-Female-HD  [DB15-VGA-Female]
J4  8918-P6  [PS2-6PIN]
J5  8918-P6  [PS2-6PIN]
R10  680R  [CC2012-0805]
R11  330R  [CC2012-0805]
R12  680R  [CC2012-0805]
R13  330R  [CC2012-0805]
R14  680R  [CC2012-0805]
R15  330R  [CC2012-0805]
RA2  4K7  [MNR34]

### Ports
BLUE0 (in), BLUE1 (in), GREEN0 (in), GREEN1 (in), HDRIVE (in), KBCLOCK (in), KBDATA (bidir), MOUSECLOCK (in), MOUSEDATA (bidir), RED0 (in), RED1 (in), VDRIVE (in)

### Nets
GND: C5.2 D1.1 D2.1 D3.1 D4.1 D5.1 J3.5 J3.6 J3.7 J3.8 J3.10 J3.16(MH1) J3.17(MH2) J4.3 J4.S J5.3 J5.S
VCC: C5.1 D1.2 D2.2 D3.2 D4.2 D5.2 J4.4 J5.4 RA2.5 RA2.6 RA2.7 RA2.8
BLUE0: R14.1 ; port BLUE0
BLUE1: R15.1 ; port BLUE1
BLUE#: D3.3 J3.3 R14.2 R15.2
GREEN0: R12.1 ; port GREEN0
GREEN1: R13.1 ; port GREEN1
GREEN#: D2.3 J3.2 R12.2 R13.2
HDRIVE: D4.3 J3.13 ; port HDRIVE
KBCLOCK: J4.5 RA2.1 ; port KBCLOCK
KBDATA: J4.1 RA2.2 ; port KBDATA
MOUSECLOCK: J5.5 RA2.3 ; port MOUSECLOCK
MOUSEDATA: J5.1 RA2.4 ; port MOUSEDATA
RED0: R10.1 ; port RED0
RED1: R11.1 ; port RED1
RED#: D1.3 J3.1 R10.2 R11.2
VDRIVE: D5.3 J3.14 ; port VDRIVE

Not connected (* = marked no-connect by the designer): J3 4 9 11 12 15; J4 2 6; J5 2 6

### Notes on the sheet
- VGA
- (near J4) PS2 KEYBOARD
- (near J5) PS2 MOUSE

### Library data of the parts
C5 = CAP_POLAR: Polar Capacitor; Fitted: True
D1-D5 = BAS40-04: Shottky Diode Pair; Fitted: True
J3 = Dsub-15-Female-HD: Dsub-15 High density VGA Female connetor; Manufacturer: Generic Components; Package Information: Latest Revision: E; Class I: Connector; Positions: 30; Gender: Receptacle Header; Fitted: True
J4 J5 = PS2-6PIN: 6 Pin Through Hole PS2 Socket (Kycon P/N); Fitted: True
R10-R15 = RES: Resistor; Fitted: True
RA2 = MNR34: 3216x4 Resistor Array; Fitted: True

## Sheet BOC_Spartan.SchDoc: Board-On-Chip Programmable Logic
size C; Organization: Altium Limited; Address1: L3, 12a Rodborough Rd; Address2: Frenchs Forest; Address3: NSW; Address4: Australia 2086; Revision: 1.06; SheetNumber: 4; SheetTotal: 16
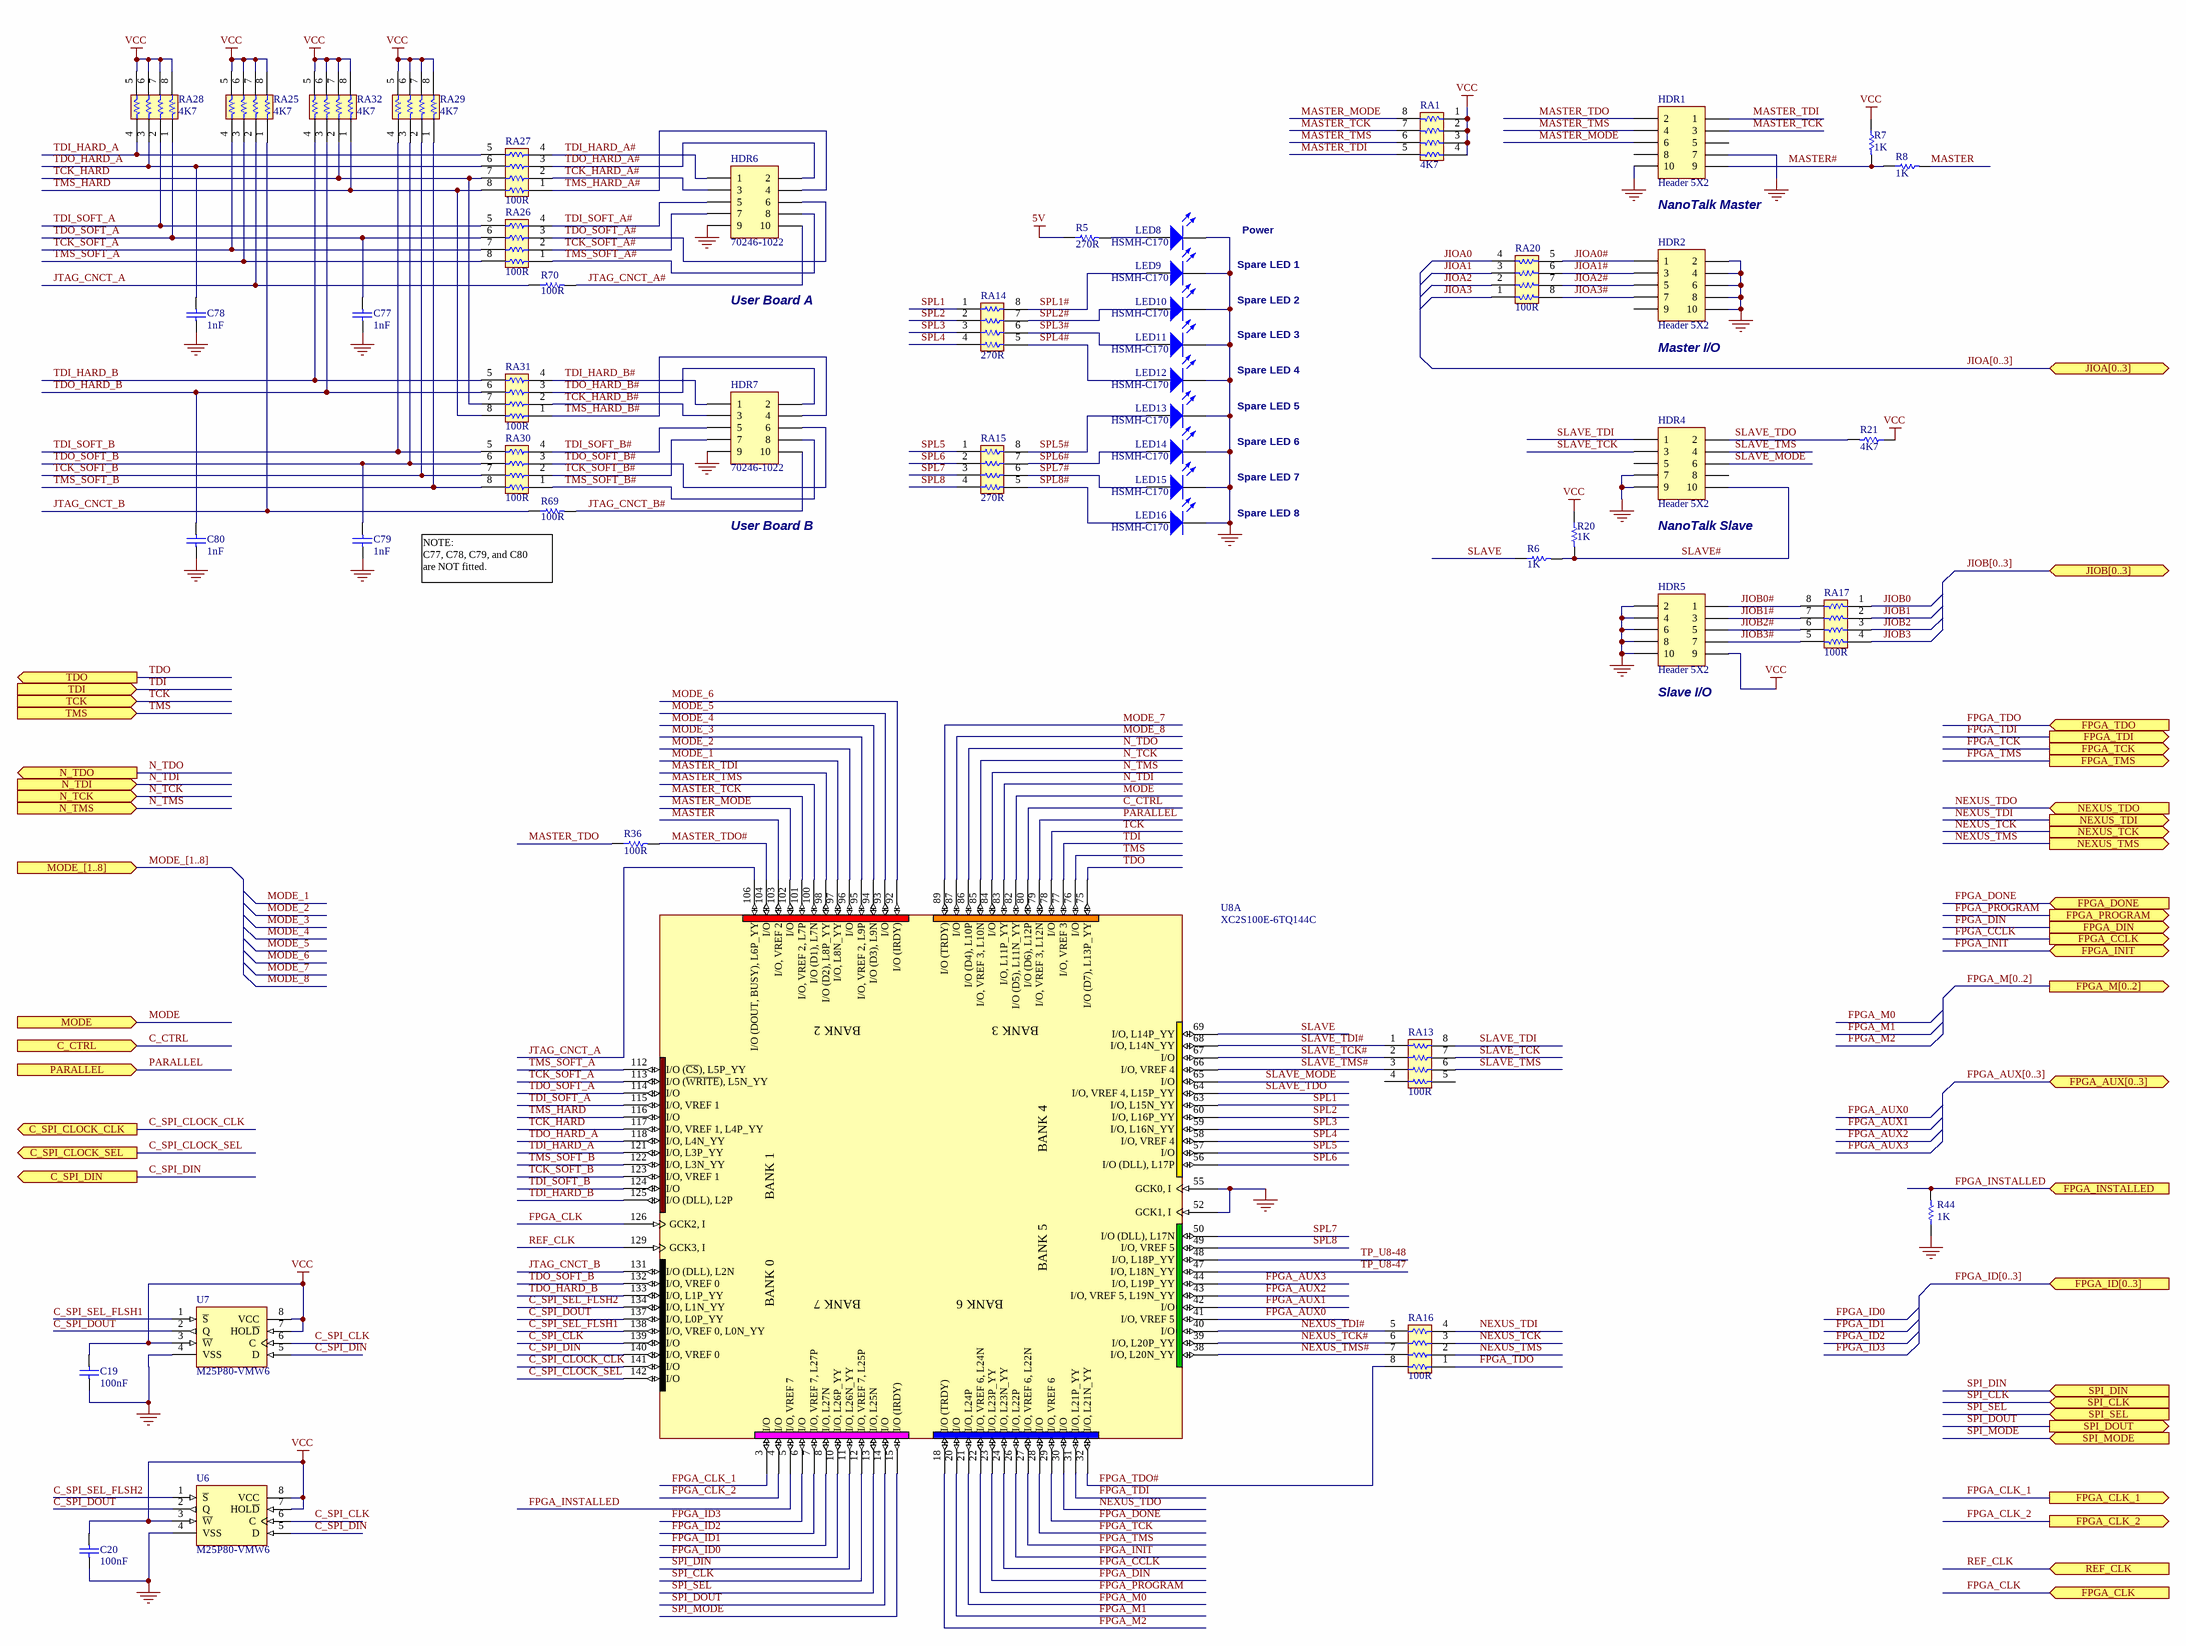
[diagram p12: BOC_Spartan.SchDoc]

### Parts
C19  100nF  [CC2012-0805]
C20  100nF  [CC2012-0805]
C77  1nF  [CC2012-0805]
C78  1nF  [CC2012-0805]
C79  1nF  [CC2012-0805]
C80  1nF  [CC2012-0805]
HDR1  Header 5X2  Usage: NanoTalk Master  [HDR2X5]
HDR2  Header 5X2  Usage: Master I/O  [HDR2X5]
HDR4  Header 5X2  Usage: NanoTalk Slave  [HDR2X5]
HDR5  Header 5X2  Usage: Slave I/O  [HDR2X5]
HDR6  70246-1022  Usage: User Board A  [HDR2X5_LP]
HDR7  70246-1022  Usage: User Board B  [HDR2X5_LP]
LED8  HSMH-C170  [SMD _LED]
LED9  HSMH-C170  [SMD _LED]
LED10  HSMH-C170  [SMD _LED]
LED11  HSMH-C170  [SMD _LED]
LED12  HSMH-C170  [SMD _LED]
LED13  HSMH-C170  [SMD _LED]
LED14  HSMH-C170  [SMD _LED]
LED15  HSMH-C170  [SMD _LED]
LED16  HSMH-C170  [SMD _LED]
R5  270R  [CC2012-0805]
R6  1K  [CC2012-0805]
R7  1K  [CC2012-0805]
R8  1K  [CC2012-0805]
R20  1K  [CC2012-0805]
R21  4K7  [CC2012-0805]
R36  100R  [CC2012-0805]
R44  1K  [CC2012-0805]
R69  100R  [CC2012-0805]
R70  100R  [CC2012-0805]
RA1  4K7  [MNR34]
RA13  100R  [MNR34]
RA14  270R  [MNR34]
RA15  270R  [MNR34]
RA16  100R  [MNR34]
RA17  100R  [MNR34]
RA20  100R  [MNR34]
RA25  4K7  [MNR34]
RA26  100R  [MNR34]
RA27  100R  [MNR34]
RA28  4K7  [MNR34]
RA29  4K7  [MNR34]
RA30  100R  [MNR34]
RA31  100R  [MNR34]
RA32  4K7  [MNR34]
U6  M25P80-VMW6  [SO8_MW/SO8_MN]
U7  M25P80-VMW6  [SO8_MW/SO8_MN]
U8  XC2S100E-6TQ144C  [TQ144]  (part A of 3)

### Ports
C_CTRL (in), C_SPI_CLOCK_CLK (out), C_SPI_CLOCK_SEL (out), C_SPI_DIN (out), FPGA_AUX[0..3] (bidir), FPGA_CCLK (out), FPGA_CLK (in), FPGA_CLK_1 (out), FPGA_CLK_2 (out), FPGA_DIN (out), FPGA_DONE (in), FPGA_ID[0..3] (in), FPGA_INIT (bidir), FPGA_INSTALLED (in), FPGA_M[0..2] (out), FPGA_PROGRAM (out), FPGA_TCK (out), FPGA_TDI (out), FPGA_TDO (in), FPGA_TMS (out), JIOA[0..3] (bidir), JIOB[0..3] (bidir), MODE (in), MODE_[1..8] (in), N_TCK (in), N_TDI (in), N_TDO (out), N_TMS (in), NEXUS_TCK (out), NEXUS_TDI (out), NEXUS_TDO (in), NEXUS_TMS (out), PARALLEL (in), REF_CLK (in), SPI_CLK (in), SPI_DIN (in), SPI_DOUT (out), SPI_MODE (in), SPI_SEL (in), TCK (in), TDI (in), TDO (out), TMS (in)

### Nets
5V: R5.1
GND: C19.1 C20.2 C77.2 C78.2 C79.2 C80.2 HDR1.7 HDR1.10 HDR2.2 HDR2.4 HDR2.6 HDR2.8 HDR2.10 HDR4.7 HDR4.9 HDR5.2 HDR5.4 HDR5.6 HDR5.8 HDR5.10 HDR6.9 HDR7.9 LED8.2(K) LED9.2(K) LED10.2(K) LED11.2(K) LED12.2(K) LED13.2(K) LED14.2(K) LED15.2(K) LED16.2(K) R44.1 U6.4(VSS) U7.4(VSS) U8.52(GCK1,_I) U8.55(GCK0,_I)
VCC: C19.2 C20.1 HDR5.9 R7.1 R20.1 R21.1 RA1.1 RA1.2 RA1.3 RA1.4 RA25.5 RA25.6 RA25.7 RA25.8 RA28.5 RA28.6 RA28.7 RA28.8 RA29.5 RA29.6 RA29.7 RA29.8 RA32.5 RA32.6 RA32.7 RA32.8 U6.3(~{W}) U6.7(HOL~{D}) U6.8(VCC) U7.3(~{W}) U7.7(HOL~{D}) U7.8(VCC)
C_CTRL: U8.80(I/O_(D6),_L12P) ; port C_CTRL
C_SPI_CLK: U6.6(C) U7.6(C) U8.139(I/O)
C_SPI_CLOCK_CLK: U8.141(I/O) ; port C_SPI_CLOCK_CLK
C_SPI_CLOCK_SEL: U8.142(I/O) ; port C_SPI_CLOCK_SEL
C_SPI_DIN: U6.5(D) U7.5(D) U8.140(I/O,_VREF_0) ; port C_SPI_DIN
C_SPI_DOUT: U6.2(Q) U7.2(Q) U8.137(I/O,_L0P_YY)
C_SPI_SEL_FLSH1: U7.1(~{S}) U8.138(I/O,_VREF_0,_L0N_YY)
C_SPI_SEL_FLSH2: U6.1(~{S}) U8.134(I/O,_L1N_YY)
FPGA_AUX0: U8.41(I/O,_VREF_5)
FPGA_AUX1: U8.42(I/O)
FPGA_AUX2: U8.43(I/O,_VREF_5,_L19N_YY)
FPGA_AUX3: U8.44(I/O,_L19P_YY)
FPGA_CCLK: U8.24(I/O,_L23N_YY) ; port FPGA_CCLK
FPGA_CLK: U8.126(GCK2,_I) ; port FPGA_CLK
FPGA_CLK_1: U8.3(I/O) ; port FPGA_CLK_1
FPGA_CLK_2: U8.4(I/O) ; port FPGA_CLK_2
FPGA_DIN: U8.23(I/O,_L23P_YY) ; port FPGA_DIN
FPGA_DONE: U8.29(I/O,_VREF_6) ; port FPGA_DONE
FPGA_ID0: U8.10(I/O,_L26P_YY)
FPGA_ID1: U8.8(I/O,_L27N)
FPGA_ID2: U8.7(I/O,_VREF_7,_L27P)
FPGA_ID3: U8.6(I/O)
FPGA_INIT: U8.26(I/O,_L22P) ; port FPGA_INIT
FPGA_INSTALLED: R44.2 U8.5(I/O,_VREF_7) ; port FPGA_INSTALLED
FPGA_M0: U8.21(I/O,_L24P)
FPGA_M1: U8.20(I/O)
FPGA_M2: U8.18(I/O_(TRDY))
FPGA_PROGRAM: U8.22(I/O,_VREF_6,_L24N) ; port FPGA_PROGRAM
FPGA_TCK: U8.28(I/O) ; port FPGA_TCK
FPGA_TDI: U8.31(I/O,_L21P_YY) ; port FPGA_TDI
FPGA_TDO: RA16.1 ; port FPGA_TDO
FPGA_TDO#: RA16.8 U8.32(I/O,_L21N_YY)
FPGA_TMS: U8.27(I/O,_VREF_6,_L22N) ; port FPGA_TMS
JIOA0: RA20.4
JIOA0#: HDR2.1 RA20.5
JIOA1: RA20.3
JIOA1#: HDR2.3 RA20.6
JIOA2: RA20.2
JIOA2#: HDR2.5 RA20.7
JIOA3: RA20.1
JIOA3#: HDR2.7 RA20.8
JIOB0: RA17.1
JIOB0#: HDR5.1 RA17.8
JIOB1: RA17.2
JIOB1#: HDR5.3 RA17.7
JIOB2: RA17.3
JIOB2#: HDR5.5 RA17.6
JIOB3: RA17.4
JIOB3#: HDR5.7 RA17.5
JTAG_CNCT_A: R70.1 RA25.2 U8.106(I/O_(DOUT,_BUSY),_L6P_YY)
JTAG_CNCT_A#: HDR6.10 R70.2
JTAG_CNCT_B: R69.1 RA25.1 U8.131(I/O_(DLL),_L2N)
JTAG_CNCT_B#: HDR7.10 R69.2
MASTER: R8.2 U8.103(I/O,_VREF_2)
MASTER#: HDR1.9 R7.2 R8.1
MASTER_MODE: HDR1.6 RA1.8 U8.102(I/O)
MASTER_TCK: HDR1.3 RA1.7 U8.101(I/O,_VREF_2,_L7P)
MASTER_TDI: HDR1.1 RA1.5 U8.98(I/O_(D2),_L8P_YY)
MASTER_TDO: HDR1.2 R36.1
MASTER_TDO#: R36.2 U8.104(I/O)
MASTER_TMS: HDR1.4 RA1.6 U8.100(I/O_(D1),_L7N)
MODE: U8.82(I/O_(D5),_L11N_YY) ; port MODE
MODE_1: U8.97(I/O,_L8N_YY)
MODE_2: U8.96(I/O)
MODE_3: U8.95(I/O,_VREF_2,_L9P)
MODE_4: U8.94(I/O_(D3),_L9N)
MODE_5: U8.93(I/O)
MODE_6: U8.92(I/O_(IRDY))
MODE_7: U8.89(I/O_(TRDY))
MODE_8: U8.87(I/O)
N_TCK: U8.85(I/O,_VREF_3,_L10N) ; port N_TCK
N_TDI: U8.83(I/O,_L11P_YY) ; port N_TDI
N_TDO: U8.86(I/O_(D4),_L10P) ; port N_TDO
N_TMS: U8.84(I/O) ; port N_TMS
NEXUS_TCK: RA16.3 ; port NEXUS_TCK
NEXUS_TCK#: RA16.6 U8.39(I/O,_L20P_YY)
NEXUS_TDI: RA16.4 ; port NEXUS_TDI
NEXUS_TDI#: RA16.5 U8.40(I/O)
NEXUS_TDO: U8.30(I/O) ; port NEXUS_TDO
NEXUS_TMS: RA16.2 ; port NEXUS_TMS
NEXUS_TMS#: RA16.7 U8.38(I/O,_L20N_YY)
PARALLEL: U8.79(I/O,_VREF_3,_L12N) ; port PARALLEL
REF_CLK: U8.129(GCK3,_I) ; port REF_CLK
SLAVE: R6.1 U8.69(I/O,_L14P_YY)
SLAVE#: HDR4.10 R6.2 R20.2
SLAVE_MODE: HDR4.6 U8.65(I/O)
SLAVE_TCK: HDR4.3 RA13.7
SLAVE_TCK#: RA13.2 U8.67(I/O)
SLAVE_TDI: HDR4.1 RA13.8
SLAVE_TDI#: RA13.1 U8.68(I/O,_L14N_YY)
SLAVE_TDO: HDR4.2 R21.2 U8.64(I/O,_VREF_4,_L15P_YY)
SLAVE_TMS: HDR4.4 RA13.6
SLAVE_TMS#: RA13.3 U8.66(I/O,_VREF_4)
SPI_CLK: U8.12(I/O,_VREF_7,_L25P) ; port SPI_CLK
SPI_DIN: U8.11(I/O,_L26N_YY) ; port SPI_DIN
SPI_DOUT: U8.14(I/O) ; port SPI_DOUT
SPI_MODE: U8.15(I/O_(IRDY)) ; port SPI_MODE
SPI_SEL: U8.13(I/O,_L25N) ; port SPI_SEL
SPL1: RA14.1 U8.63(I/O,_L15N_YY)
SPL1#: LED9.1(A) RA14.8
SPL2: RA14.2 U8.60(I/O,_L16P_YY)
SPL2#: LED10.1(A) RA14.7
SPL3: RA14.3 U8.59(I/O,_L16N_YY)
SPL3#: LED11.1(A) RA14.6
SPL4: RA14.4 U8.58(I/O,_VREF_4)
SPL4#: LED12.1(A) RA14.5
SPL5: RA15.1 U8.57(I/O)
SPL5#: LED13.1(A) RA15.8
SPL6: RA15.2 U8.56(I/O_(DLL),_L17P)
SPL6#: LED14.1(A) RA15.7
SPL7: RA15.3 U8.50(I/O_(DLL),_L17N)
SPL7#: LED15.1(A) RA15.6
SPL8: RA15.4 U8.49(I/O,_VREF_5)
SPL8#: LED16.1(A) RA15.5
TCK: U8.78(I/O) ; port TCK
TCK_HARD: RA27.7 RA31.7 RA32.2 U8.117(I/O,_VREF_1,_L4P_YY)
TCK_HARD_A#: HDR6.3 RA27.2
TCK_HARD_B#: HDR7.3 RA31.2
TCK_SOFT_A: RA25.4 RA26.7 U8.113(I/O_(~{WRITE}),_L5N_YY)
TCK_SOFT_A#: HDR6.7 RA26.2
TCK_SOFT_B: RA29.2 RA30.7 U8.123(I/O,_VREF_1)
TCK_SOFT_B#: HDR7.7 RA30.2
TDI: U8.77(I/O,_VREF_3) ; port TDI
TDI_HARD_A: RA27.5 RA28.4 U8.121(I/O,_L3P_YY)
TDI_HARD_A#: HDR6.1 RA27.4
TDI_HARD_B: RA31.5 RA32.4 U8.125(I/O_(DLL),_L2P)
TDI_HARD_B#: HDR7.1 RA31.4
TDI_SOFT_A: RA26.5 RA28.2 U8.115(I/O,_VREF_1)
TDI_SOFT_A#: HDR6.5 RA26.4
TDI_SOFT_B: RA29.4 RA30.5 U8.124(I/O)
TDI_SOFT_B#: HDR7.5 RA30.4
TDO: U8.75(I/O_(D7),_L13P_YY) ; port TDO
TDO_HARD_A: C78.1 RA27.6 RA28.3 U8.118(I/O,_L4N_YY)
TDO_HARD_A#: HDR6.2 RA27.3
TDO_HARD_B: C80.1 RA31.6 RA32.3 U8.133(I/O,_L1P_YY)
TDO_HARD_B#: HDR7.2 RA31.3
TDO_SOFT_A: C77.1 RA26.6 RA28.1 U8.114(I/O)
TDO_SOFT_A#: HDR6.6 RA26.3
TDO_SOFT_B: C79.1 RA29.3 RA30.6 U8.132(I/O,_VREF_0)
TDO_SOFT_B#: HDR7.6 RA30.3
TMS: U8.76(I/O) ; port TMS
TMS_HARD: RA27.8 RA31.8 RA32.1 U8.116(I/O)
TMS_HARD_A#: HDR6.4 RA27.1
TMS_HARD_B#: HDR7.4 RA31.1
TMS_SOFT_A: RA25.3 RA26.8 U8.112(I/O_(~{CS}),_L5P_YY)
TMS_SOFT_A#: HDR6.8 RA26.1
TMS_SOFT_B: RA29.1 RA30.8 U8.122(I/O,_L3N_YY)
TMS_SOFT_B#: HDR7.8 RA30.1
TP_U8-47: U8.47(I/O,_L18N_YY)
TP_U8-48: U8.48(I/O,_L18P_YY)
NetLED8_1: LED8.1(A) R5.2

Not connected (* = marked no-connect by the designer): HDR1 5 8; HDR2 9; HDR4 5 8; RA13 4 5

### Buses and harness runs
bus FPGA_AUX[0..3] = port FPGA_AUX[0..3]
bus FPGA_ID[0..3] = port FPGA_ID[0..3]
bus FPGA_M[0..2] = port FPGA_M[0..2]
bus JIOA[0..3] = port JIOA[0..3]
bus JIOB[0..3] = port JIOB[0..3]
bus MODE_[1..8] = port MODE_[1..8]

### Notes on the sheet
- Spare LED 1
- Power
- Spare LED 2
- Spare LED 3
- Spare LED 4
- Spare LED 5
- Spare LED 6
- Spare LED 7
- Spare LED 8
- (near R69) NOTE:
  C77, C78, C79, and C80
  are NOT fitted.

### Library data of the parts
C19 C20 = CAP: Capacitor; Fitted: True
C77-C80 = CAP: Capacitor; Fitted: False
HDR1 HDR2 HDR4 HDR5 = Header 5X2: Header, 5-Pin, Dual row; Manufacturer: Generic Components; Class I: Connector; Fitted: True
HDR6 HDR7 = Header 5X2: Header, 5-Pin, Dual row; Manufacturer: Molex; Class I: Connector; Fitted: True
LED8-LED16 = HSMX-C670: as LED0 on sheet BOC_LED_DIPSWITCH
R5-R8 R20 R21 R36 R44 R69 R70 = RES: Resistor; Fitted: True
RA1 RA13-RA17 RA20 RA25-RA32 = MNR34: 3216x4 Resistor Array; Fitted: True
U6 = M25P10-VMN6: 8 Mbit Flash Serial Prom; Fitted: True
U7 = M25P20-VMN6: 8 Mbit Flash Serial Prom; Fitted: True
U8 = XC2S100E-6TQ144C: Spartan-IIE 1.8V FPGA, 144-Pin TQFP, Standard Performance, Commercial Grade; Manufacturer: Xilinx; Package Information: Latest Revision: ver1.1, Oct-2002; Class I: Field Programmable Gate Array; Code - JEDEC: MS-026-BFB; Code - IPC: SQFP20X20-144; Fitted: True

## Sheet BOC_DAUGHTER.SchDoc: Board-On-Chip Daughter Connectors
size B; Organization: Altium Limited; Address1: L3, 12a Rodborough Rd; Address2: Frenchs Forest; Address3: NSW; Address4: Australia 2086; Revision: 1.06; SheetNumber: 8; SheetTotal: 16
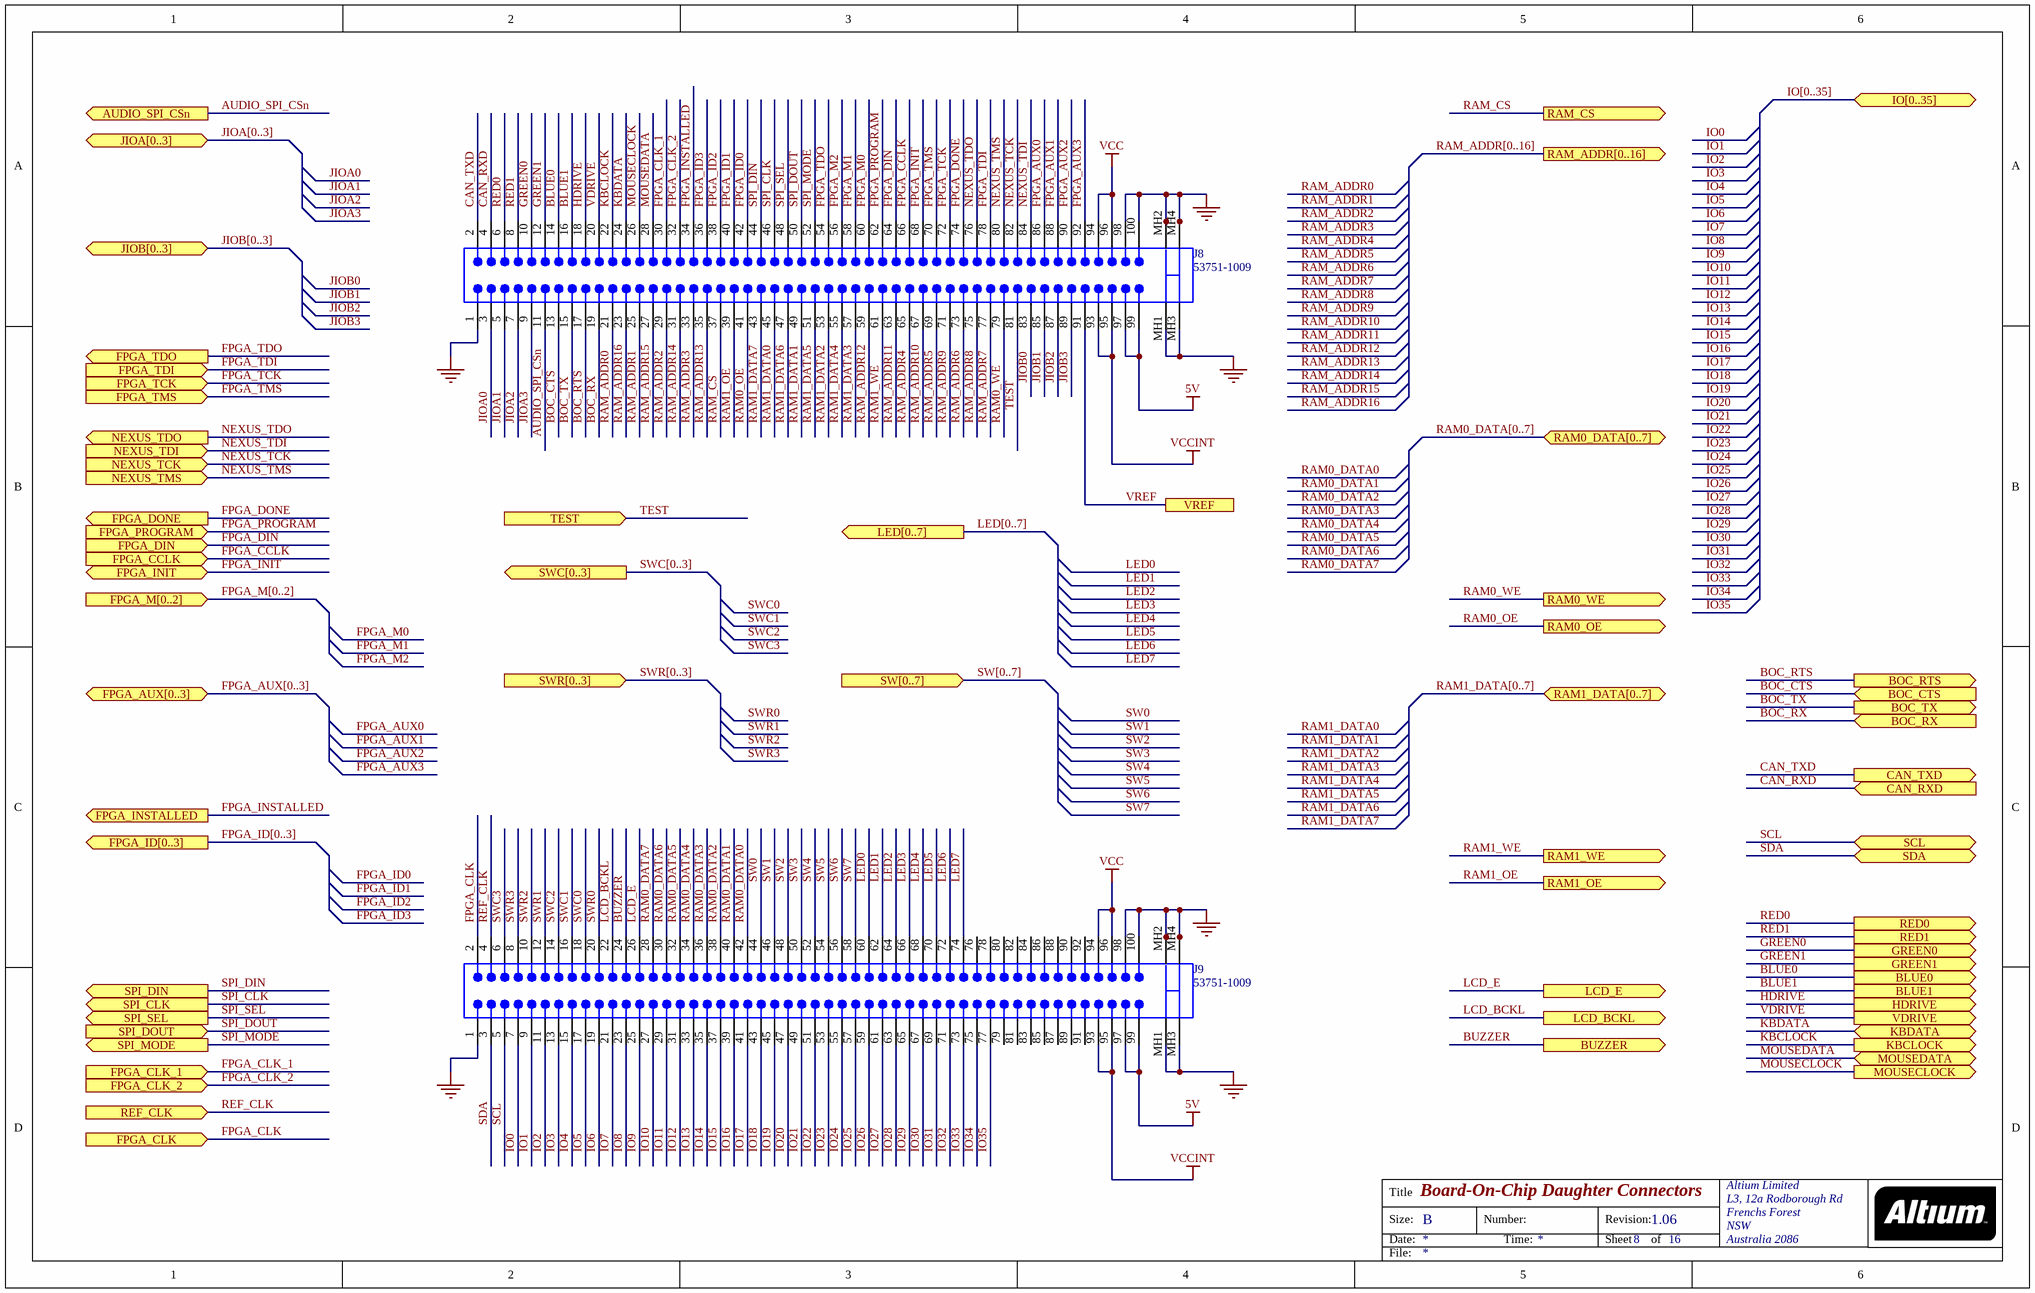
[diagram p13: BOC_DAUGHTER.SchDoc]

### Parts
J8  53751-1009  [53751]
J9  53751-1009  [53751]

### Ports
AUDIO_SPI_CSn (out), BLUE0 (out), BLUE1 (out), BOC_CTS (in), BOC_RTS (out), BOC_RX (in), BOC_TX (out), BUZZER (out), CAN_RXD (in), CAN_TXD (out), FPGA_AUX[0..3] (bidir), FPGA_CCLK (in), FPGA_CLK (in), FPGA_CLK_1 (in), FPGA_CLK_2 (in), FPGA_DIN (in), FPGA_DONE (out), FPGA_ID[0..3] (out), FPGA_INIT (bidir), FPGA_INSTALLED (out), FPGA_M[0..2] (in), FPGA_PROGRAM (in), FPGA_TCK (in), FPGA_TDI (in), FPGA_TDO (out), FPGA_TMS (in), GREEN0 (out), GREEN1 (out), HDRIVE (out), IO[0..35] (bidir), JIOA[0..3] (bidir), JIOB[0..3] (bidir), KBCLOCK (out), KBDATA (bidir), LCD_BCKL (out), LCD_E (out), LED[0..7] (out), MOUSECLOCK (out), MOUSEDATA (bidir), NEXUS_TCK (in), NEXUS_TDI (in), NEXUS_TDO (out), NEXUS_TMS (in), RAM0_DATA[0..7] (bidir), RAM0_OE (out), RAM0_WE (out), RAM1_DATA[0..7] (bidir), RAM1_OE (out), RAM1_WE (out), RAM_ADDR[0..16] (out), RAM_CS (out), RED0 (out), RED1 (out), REF_CLK (in), SCL (bidir), SDA (bidir), SPI_CLK (out), SPI_DIN (out), SPI_DOUT (in), SPI_MODE (out), SPI_SEL (out), SW[0..7] (in), SWC[0..3] (out), SWR[0..3] (in), TEST (in), VDRIVE (out), VREF

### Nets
5V: J8.97 J8.99 J9.97 J9.99
GND: J8.1 J8.98 J8.100 J8.MH1 J8.MH2 J8.MH2A J8.MH2B J8.MH3 J8.MH4 J8.MH4A J8.MH4B J9.1 J9.98 J9.100 J9.MH1 J9.MH2 J9.MH2A J9.MH2B J9.MH3 J9.MH4 J9.MH4A J9.MH4B
VCC: J8.94 J8.96 J9.94 J9.96
VCCINT: J8.93 J8.95 J9.93 J9.95
AUDIO_SPI_CSn: J8.11 ; port AUDIO_SPI_CSn
BLUE0: J8.14 ; port BLUE0
BLUE1: J8.16 ; port BLUE1
BOC_CTS: J8.13 ; port BOC_CTS
BOC_RTS: J8.17 ; port BOC_RTS
BOC_RX: J8.19 ; port BOC_RX
BOC_TX: J8.15 ; port BOC_TX
BUZZER: J9.24 ; port BUZZER
CAN_RXD: J8.4 ; port CAN_RXD
CAN_TXD: J8.2 ; port CAN_TXD
FPGA_AUX0: J8.86
FPGA_AUX1: J8.88
FPGA_AUX2: J8.90
FPGA_AUX3: J8.92
FPGA_CCLK: J8.66 ; port FPGA_CCLK
FPGA_CLK: J9.2 ; port FPGA_CLK
FPGA_CLK_1: J8.30 ; port FPGA_CLK_1
FPGA_CLK_2: J8.32 ; port FPGA_CLK_2
FPGA_DIN: J8.64 ; port FPGA_DIN
FPGA_DONE: J8.74 ; port FPGA_DONE
FPGA_ID0: J8.42
FPGA_ID1: J8.40
FPGA_ID2: J8.38
FPGA_ID3: J8.36
FPGA_INIT: J8.68 ; port FPGA_INIT
FPGA_INSTALLED: J8.34 ; port FPGA_INSTALLED
FPGA_M0: J8.60
FPGA_M1: J8.58
FPGA_M2: J8.56
FPGA_PROGRAM: J8.62 ; port FPGA_PROGRAM
FPGA_TCK: J8.72 ; port FPGA_TCK
FPGA_TDI: J8.78 ; port FPGA_TDI
FPGA_TDO: J8.54 ; port FPGA_TDO
FPGA_TMS: J8.70 ; port FPGA_TMS
GREEN0: J8.10 ; port GREEN0
GREEN1: J8.12 ; port GREEN1
HDRIVE: J8.18 ; port HDRIVE
IO0: J9.7
IO1: J9.9
IO2: J9.11
IO3: J9.13
IO4: J9.15
IO5: J9.17
IO6: J9.19
IO7: J9.21
IO8: J9.23
IO9: J9.25
IO10: J9.27
IO11: J9.29
IO12: J9.31
IO13: J9.33
IO14: J9.35
IO15: J9.37
IO16: J9.39
IO17: J9.41
IO18: J9.43
IO19: J9.45
IO20: J9.47
IO21: J9.49
IO22: J9.51
IO23: J9.53
IO24: J9.55
IO25: J9.57
IO26: J9.59
IO27: J9.61
IO28: J9.63
IO29: J9.65
IO30: J9.67
IO31: J9.69
IO32: J9.71
IO33: J9.73
IO34: J9.75
IO35: J9.77
JIOA0: J8.3
JIOA1: J8.5
JIOA2: J8.7
JIOA3: J8.9
JIOB0: J8.83
JIOB1: J8.85
JIOB2: J8.87
JIOB3: J8.89
KBCLOCK: J8.22 ; port KBCLOCK
KBDATA: J8.24 ; port KBDATA
LCD_BCKL: J9.22 ; port LCD_BCKL
LCD_E: J9.26 ; port LCD_E
LED0: J9.60
LED1: J9.62
LED2: J9.64
LED3: J9.66
LED4: J9.68
LED5: J9.70
LED6: J9.72
LED7: J9.74
MOUSECLOCK: J8.26 ; port MOUSECLOCK
MOUSEDATA: J8.28 ; port MOUSEDATA
NEXUS_TCK: J8.82 ; port NEXUS_TCK
NEXUS_TDI: J8.84 ; port NEXUS_TDI
NEXUS_TDO: J8.76 ; port NEXUS_TDO
NEXUS_TMS: J8.80 ; port NEXUS_TMS
RAM0_DATA0: J9.42
RAM0_DATA1: J9.40
RAM0_DATA2: J9.38
RAM0_DATA3: J9.36
RAM0_DATA4: J9.34
RAM0_DATA5: J9.32
RAM0_DATA6: J9.30
RAM0_DATA7: J9.28
RAM0_OE: J8.41 ; port RAM0_OE
RAM0_WE: J8.79 ; port RAM0_WE
RAM1_DATA0: J8.45
RAM1_DATA1: J8.49
RAM1_DATA2: J8.53
RAM1_DATA3: J8.57
RAM1_DATA4: J8.55
RAM1_DATA5: J8.51
RAM1_DATA6: J8.47
RAM1_DATA7: J8.43
RAM1_OE: J8.39 ; port RAM1_OE
RAM1_WE: J8.61 ; port RAM1_WE
RAM_ADDR0: J8.21
RAM_ADDR1: J8.25
RAM_ADDR2: J8.29
RAM_ADDR3: J8.33
RAM_ADDR4: J8.65
RAM_ADDR5: J8.69
RAM_ADDR6: J8.73
RAM_ADDR7: J8.77
RAM_ADDR8: J8.75
RAM_ADDR9: J8.71
RAM_ADDR10: J8.67
RAM_ADDR11: J8.63
RAM_ADDR12: J8.59
RAM_ADDR13: J8.35
RAM_ADDR14: J8.31
RAM_ADDR15: J8.27
RAM_ADDR16: J8.23
RAM_CS: J8.37 ; port RAM_CS
RED0: J8.6 ; port RED0
RED1: J8.8 ; port RED1
REF_CLK: J9.4 ; port REF_CLK
SCL: J9.5 ; port SCL
SDA: J9.3 ; port SDA
SPI_CLK: J8.46 ; port SPI_CLK
SPI_DIN: J8.44 ; port SPI_DIN
SPI_DOUT: J8.50 ; port SPI_DOUT
SPI_MODE: J8.52 ; port SPI_MODE
SPI_SEL: J8.48 ; port SPI_SEL
SW0: J9.44
SW1: J9.46
SW2: J9.48
SW3: J9.50
SW4: J9.52
SW5: J9.54
SW6: J9.56
SW7: J9.58
SWC0: J9.18
SWC1: J9.16
SWC2: J9.14
SWC3: J9.6
SWR0: J9.20
SWR1: J9.12
SWR2: J9.10
SWR3: J9.8
TEST: J8.81 ; port TEST
VDRIVE: J8.20 ; port VDRIVE
VREF: J8.91 ; port VREF

Not connected (* = marked no-connect by the designer): J9 76 78 79 80 81 82 83 84 85 86 87 88 89 90 91 92

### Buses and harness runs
bus FPGA_AUX[0..3] = port FPGA_AUX[0..3]
bus FPGA_ID[0..3] = port FPGA_ID[0..3]
bus FPGA_M[0..2] = port FPGA_M[0..2]
bus IO[0..35] = port IO[0..35]
bus JIOA[0..3] = port JIOA[0..3]
bus JIOB[0..3] = port JIOB[0..3]
bus LED[0..7] = port LED[0..7]
bus RAM0_DATA[0..7] = port RAM0_DATA[0..7]
bus RAM1_DATA[0..7] = port RAM1_DATA[0..7]
bus RAM_ADDR[0..16] = port RAM_ADDR[0..16]
bus SW[0..7] = port SW[0..7]
bus SWC[0..3] = port SWC[0..3]
bus SWR[0..3] = port SWR[0..3]

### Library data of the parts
J8 J9 = 53751-1009: Board-to-Board, Docking Station, 0.80mm (.031") Pitch, Shielded Plug, Vertical, Ultra Low Profile, SMT; Manufacturer: Molex; Package Information: Latest Revision: Jun-2001; Mating Height: 8.5mm; Voltage: 100V; Current: 0.5A; Contact Resistance: 40mOhm max; PCB Layout: Complies with Manufacturer's Recommendation.; Fitted: True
